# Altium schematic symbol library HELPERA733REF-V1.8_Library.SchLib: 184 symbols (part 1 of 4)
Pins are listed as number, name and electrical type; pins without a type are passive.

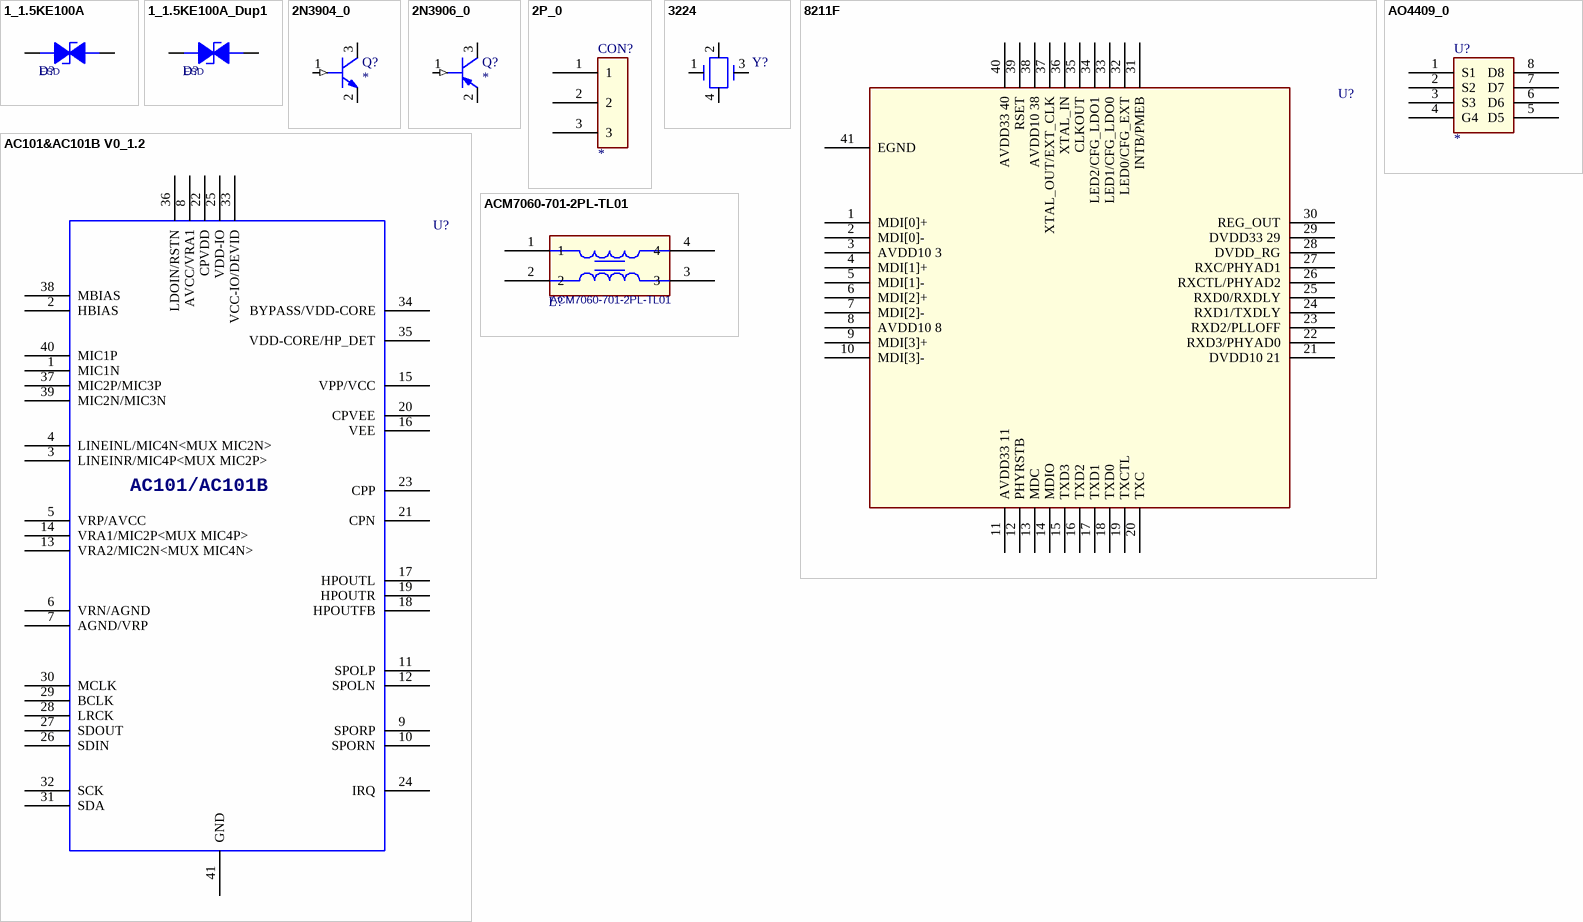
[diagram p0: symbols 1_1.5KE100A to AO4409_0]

## 1_1.5KE100A
designator D?, comment ESD
pins: 1 ANODE, 2 CATHODE

## 1_1.5KE100A_Dup1
designator D?, comment ESD
pins: 1 ANODE, 2 CATHODE

## 2N3904_0
designator Q?
pins: 1 BASE (in), 2 EMITTER, 3 COLLECTOR

## 2N3906_0
designator Q?
pins: 1 BASE (in), 2 EMITTER, 3 COLLECTOR

## 2P_0
designator CON?
pins: 1, 2, 3

## 3224
designator Y?, comment 25M-10pF-30ppm  (value not drawn)
Parameter: 插件无源晶振，HC-49S; ID: CR-S-P0019
pins: 1, 2, 3, 4

## 8211F
designator U?, comment RTL8211F-CG/RTL8211FD-CG  (value not drawn)
ID: OT-IC0192; Parameter: QFN40
pins: 1 MDI[0]+, 2 MDI[0]-, 3 AVDD10 3, 4 MDI[1]+, 5 MDI[1]-, 6 MDI[2]+, 7 MDI[2]-, 8 AVDD10 8, 9 MDI[3]+, 10 MDI[3]-, 11 AVDD33 11, 12 PHYRSTB, 13 MDC, 14 MDIO, 15 TXD3, 16 TXD2, 17 TXD1, 18 TXD0, 19 TXCTL, 20 TXC, 21 DVDD10 21, 22 RXD3/PHYAD0, 23 RXD2/PLLOFF, 24 RXD1/TXDLY, 25 RXD0/RXDLY, 26 RXCTL/PHYAD2, 27 RXC/PHYAD1, 28 DVDD_RG, 29 DVDD33 29, 30 REG_OUT, 31 INTB/PMEB, 32 LED0/CFG_EXT, 33 LED1/CFG_LDO0, 34 LED2/CFG_LDO1, 35 CLKOUT, 36 XTAL_IN, 37 XTAL_OUT/EXT_CLK, 38 AVDD10 38, 39 RSET, 40 AVDD33 40, 41 EGND

## AC101&AC101B V0_1.2
designator U?, comment AXP22x  (value not drawn)
pins: 1 MIC1N, 2 HBIAS, 3 LINEINR/MIC4P<MUX MIC2P>, 4 LINEINL/MIC4N<MUX MIC2N>, 5 VRP/AVCC, 6 VRN/AGND, 7 AGND/VRP, 8 AVCC/VRA1, 9 SPORP, 10 SPORN, 11 SPOLP, 12 SPOLN, 13 VRA2/MIC2N<MUX MIC4N>, 14 VRA1/MIC2P<MUX MIC4P>, 15 VPP/VCC, 16 VEE, 17 HPOUTL, 18 HPOUTFB, 19 HPOUTR, 20 CPVEE, 21 CPN, 22 CPVDD, 23 CPP, 24 IRQ, 25 VDD-IO, 26 SDIN, 27 SDOUT, 28 LRCK, 29 BCLK, 30 MCLK, 31 SDA, 32 SCK, 33 VCC-IO/DEVID, 34 BYPASS/VDD-CORE, 35 VDD-CORE/HP_DET, 36 LDOIN/RSTN, 37 MIC2P/MIC3P, 38 MBIAS, 39 MIC2N/MIC3N, 40 MIC1P, 41 GND

## ACM7060-701-2PL-TL01
designator L?
footprint SMD_7x6mm
pins: 1, 2, 3, 4

## AO4409_0
designator U?
pins: 1 S1, 2 S2, 3 S3, 4 G4, 5 D5, 6 D6, 7 D7, 8 D8

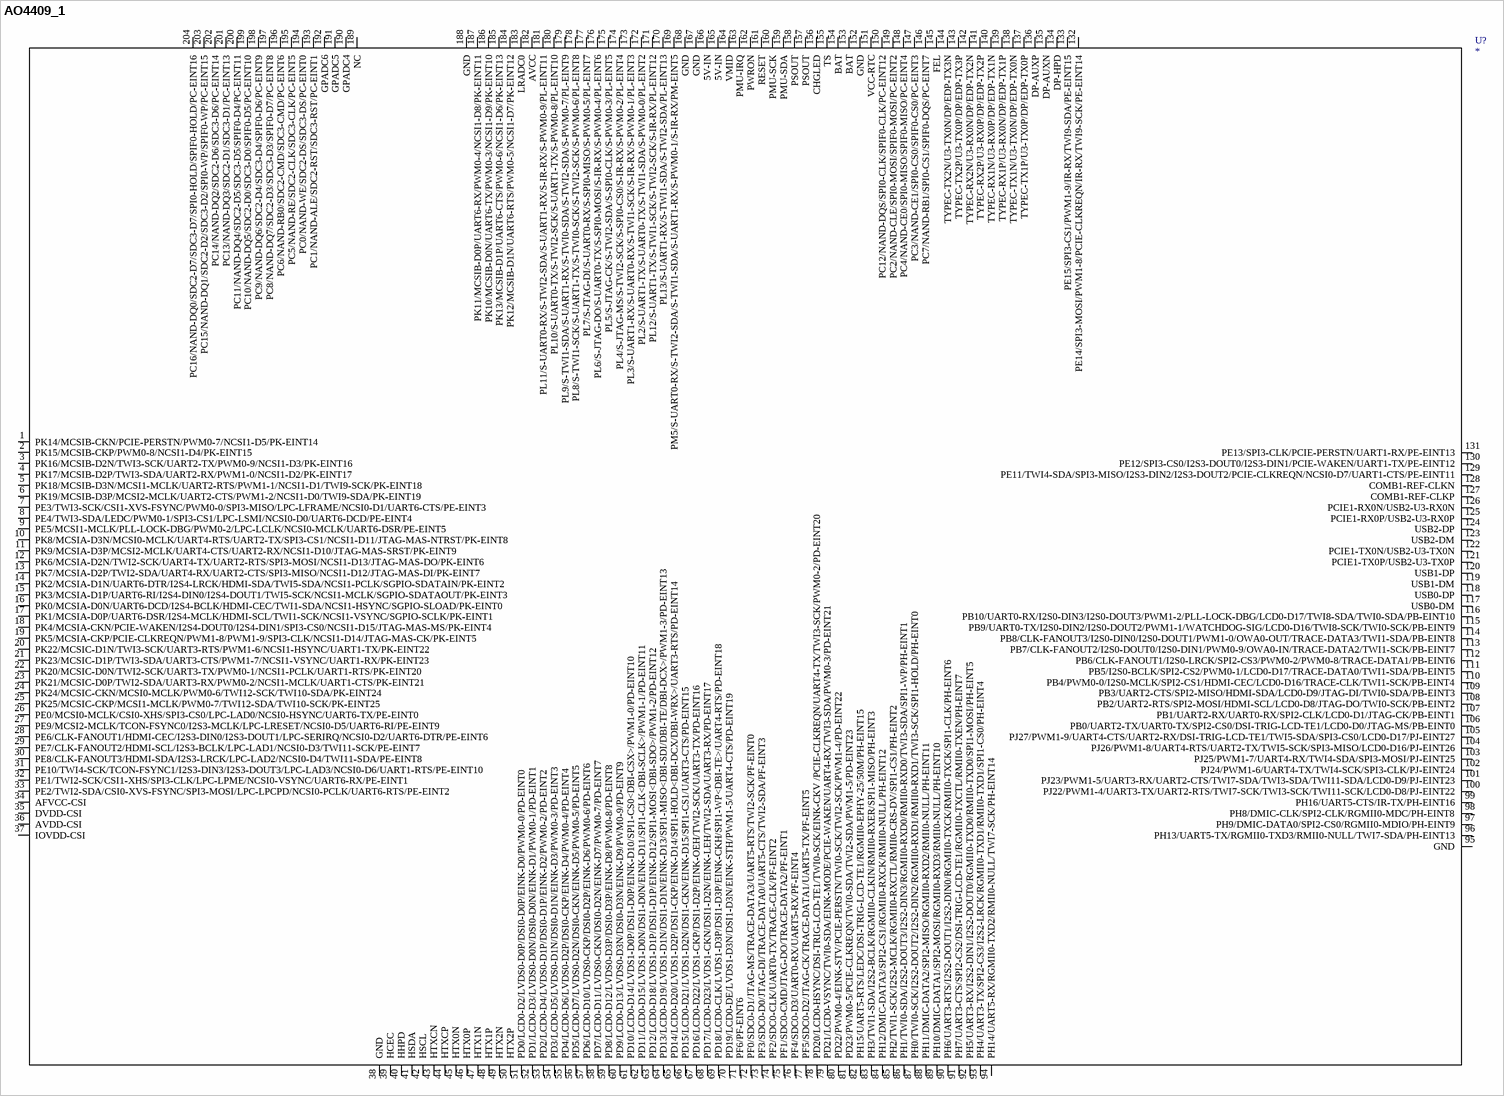
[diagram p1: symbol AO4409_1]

## AO4409_1
designator U?
pins: 1 PK14/MCSIB-CKN/PCIE-PERSTN/PWM0-7/NCSI1-D5/PK-EINT14, 2 PK15/MCSIB-CKP/PWM0-8/NCSI1-D4/PK-EINT15, 3 PK16/MCSIB-D2N/TWI3-SCK/UART2-TX/PWM0-9/NCSI1-D3/PK-EINT16, 4 PK17/MCSIB-D2P/TWI3-SDA/UART2-RX/PWM1-0/NCSI1-D2/PK-EINT17, 5 PK18/MCSIB-D3N/MCSI1-MCLK/UART2-RTS/PWM1-1/NCSI1-D1/TWI9-SCK/PK-EINT18, 6 PK19/MCSIB-D3P/MCSI2-MCLK/UART2-CTS/PWM1-2/NCSI1-D0/TWI9-SDA/PK-EINT19, 7 PE3/TWI3-SCK/CSI1-XVS-FSYNC/PWM0-0/SPI3-MISO/LPC-LFRAME/NCSI0-D1/UART6-CTS/PE-EINT3, 8 PE4/TWI3-SDA/LEDC/PWM0-1/SPI3-CS1/LPC-LSMI/NCSI0-D0/UART6-DCD/PE-EINT4, 9 PE5/MCSI1-MCLK/PLL-LOCK-DBG/PWM0-2/LPC-LCLK/NCSI0-MCLK/UART6-DSR/PE-EINT5, 10 PK8/MCSIA-D3N/MCSI0-MCLK/UART4-RTS/UART2-TX/SPI3-CS1/NCSI1-D11/JTAG-MAS-NTRST/PK-EINT8, 11 PK9/MCSIA-D3P/MCSI2-MCLK/UART4-CTS/UART2-RX/NCSI1-D10/JTAG-MAS-SRST/PK-EINT9, 12 PK6/MCSIA-D2N/TWI2-SCK/UART4-TX/UART2-RTS/SPI3-MOSI/NCSI1-D13/JTAG-MAS-DO/PK-EINT6, 13 PK7/MCSIA-D2P/TWI2-SDA/UART4-RX/UART2-CTS/SPI3-MISO/NCSI1-D12/JTAG-MAS-DI/PK-EINT7, 14 PK2/MCSIA-D1N/UART6-DTR/I2S4-LRCK/HDMI-SDA/TWI5-SDA/NCSI1-PCLK/SGPIO-SDATAIN/PK-EINT2, 15 PK3/MCSIA-D1P/UART6-RI/I2S4-DIN0/I2S4-DOUT1/TWI5-SCK/NCSI1-MCLK/SGPIO-SDATAOUT/PK-EINT3, 16 PK0/MCSIA-D0N/UART6-DCD/I2S4-BCLK/HDMI-CEC/TWI1-SDA/NCSI1-HSYNC/SGPIO-SLOAD/PK-EINT0, 17 PK1/MCSIA-D0P/UART6-DSR/I2S4-MCLK/HDMI-SCL/TWI1-SCK/NCSI1-VSYNC/SGPIO-SCLK/PK-EINT1, 18 PK4/MCSIA-CKN/PCIE-WAKEN/I2S4-DOUT0/I2S4-DIN1/SPI3-CS0/NCSI1-D15/JTAG-MAS-MS/PK-EINT4, 19 PK5/MCSIA-CKP/PCIE-CLKREQN/PWM1-8/PWM1-9/SPI3-CLK/NCSI1-D14/JTAG-MAS-CK/PK-EINT5, 20 PK22/MCSIC-D1N/TWI3-SCK/UART3-RTS/PWM1-6/NCSI1-HSYNC/UART1-TX/PK-EINT22, 21 PK23/MCSIC-D1P/TWI3-SDA/UART3-CTS/PWM1-7/NCSI1-VSYNC/UART1-RX/PK-EINT23, 22 PK20/MCSIC-D0N/TWI2-SCK/UART3-TX/PWM0-1/NCSI1-PCLK/UART1-RTS/PK-EINT20, 23 PK21/MCSIC-D0P/TWI2-SDA/UART3-RX/PWM0-2/NCSI1-MCLK/UART1-CTS/PK-EINT21, 24 PK24/MCSIC-CKN/MCSI0-MCLK/PWM0-6/TWI12-SCK/TWI10-SDA/PK-EINT24, 25 PK25/MCSIC-CKP/MCSI1-MCLK/PWM0-7/TWI12-SDA/TWI10-SCK/PK-EINT25, 26 PE0/MCSI0-MCLK/CSI0-XHS/SPI3-CS0/LPC-LAD0/NCSI0-HSYNC/UART6-TX/PE-EINT0, 27 PE9/MCSI2-MCLK/TCON-FSYNC0/I2S3-MCLK/LPC-LRESET/NCSI0-D5/UART6-RI/PE-EINT9, 28 PE6/CLK-FANOUT1/HDMI-CEC/I2S3-DIN0/I2S3-DOUT1/LPC-SERIRQ/NCSI0-D2/UART6-DTR/PE-EINT6, 29 PE7/CLK-FANOUT2/HDMI-SCL/I2S3-BCLK/LPC-LAD1/NCSI0-D3/TWI11-SCK/PE-EINT7, 30 PE8/CLK-FANOUT3/HDMI-SDA/I2S3-LRCK/LPC-LAD2/NCSI0-D4/TWI11-SDA/PE-EINT8, 31 PE10/TWI4-SCK/TCON-FSYNC1/I2S3-DIN3/I2S3-DOUT3/LPC-LAD3/NCSI0-D6/UART1-RTS/PE-EINT10, 32 PE1/TWI2-SCK/CSI1-XHS/SPI3-CLK/LPC-LPME/NCSI0-VSYNC/UART6-RX/PE-EINT1, 33 PE2/TWI2-SDA/CSI0-XVS-FSYNC/SPI3-MOSI/LPC-LPCPD/NCSI0-PCLK/UART6-RTS/PE-EINT2, 34 AFVCC-CSI, 35 DVDD-CSI, 36 AVDD-CSI, 37 IOVDD-CSI, 38 GND, 39 HCEC, 40 HHPD, 41 HSDA, 42 HSCL, 43 HTXCN, 44 HTXCP, 45 HTX0N, 46 HTX0P, 47 HTX1N, 48 HTX1P, 49 HTX2N, 50 HTX2P, 51 PD0/LCD0-D2/LVDS0-D0P/DSI0-D0P/EINK-D0/PWM0-0/PD-EINT0, 52 PD1/LCD0-D3/LVDS0-D0N/DSI0-D0N/EINK-D1/PWM0-1/PD-EINT1, 53 PD2/LCD0-D4/LVDS0-D1P/DSI0-D1P/EINK-D2/PWM0-2/PD-EINT2, 54 PD3/LCD0-D5/LVDS0-D1N/DSI0-D1N/EINK-D3/PWM0-3/PD-EINT3, 55 PD4/LCD0-D6/LVDS0-D2P/DSI0-CKP/EINK-D4/PWM0-4/PD-EINT4, 56 PD5/LCD0-D7/LVDS0-D2N/DSI0-CKN/EINK-D5/PWM0-5/PD-EINT5, 57 PD6/LCD0-D10/LVDS0-CKP/DSI0-D2P/EINK-D6/PWM0-6/PD-EINT6, 58 PD7/LCD0-D11/LVDS0-CKN/DSI0-D2N/EINK-D7/PWM0-7/PD-EINT7, 59 PD8/LCD0-D12/LVDS0-D3P/DSI0-D3P/EINK-D8/PWM0-8/PD-EINT8, 60 PD9/LCD0-D13/LVDS0-D3N/DSI0-D3N/EINK-D9/PWM0-9/PD-EINT9, 61 PD10/LCD0-D14/LVDS1-D0P/DSI1-D0P/EINK-D10/SPI1-CS0<DBI-CSX>/PWM1-0/PD-EINT10, 62 PD11/LCD0-D15/LVDS1-D0N/DSI1-D0N/EINK-D11/SPI1-CLK<DBI-SCLK>/PWM1-1/PD-EINT11, 63 PD12/LCD0-D18/LVDS1-D1P/DSI1-D1P/EINK-D12/SPI1-MOSI<DBI-SDO>/PWM1-2/PD-EINT12, 64 PD13/LCD0-D19/LVDS1-D1N/DSI1-D1N/EINK-D13/SPI1-MISO<DBI-SDI/DBI-TE/DBI-DCX>/PWM1-3/PD-EINT13, 65 PD14/LCD0-D20/LVDS1-D2P/DSI1-CKP/EINK-D14/SPI1-HOLD<DBI-DCX/DBI-WRX>/UART3-RTS/PD-EINT14, 66 PD15/LCD0-D21/LVDS1-D2N/DSI1-CKN/EINK-D15/SPI1-CS1/UART3-CTS/PD-EINT15, 67 PD16/LCD0-D22/LVDS1-CKP/DSI1-D2P/EINK-OEH/TWI2-SCK/UART3-TX/PD-EINT16, 68 PD17/LCD0-D23/LVDS1-CKN/DSI1-D2N/EINK-LEH/TWI2-SDA/UART3-RX/PD-EINT17, 69 PD18/LCD0-CLK/LVDS1-D3P/DSI1-D3P/EINK-CKH/SPI1-WP<DBI-TE>/UART4-RTS/PD-EINT18, 70 PD19/LCD0-DE/LVDS1-D3N/DSI1-D3N/EINK-STH/PWM1-5/UART4-CTS/PD-EINT19, 71 PF6/PF-EINT6, 72 PF0/SDC0-D1/JTAG-MS/TRACE-DATA3/UART5-RTS/TWI2-SCK/PF-EINT0, 73 PF3/SDC0-D0/JTAG-DI/TRACE-DATA0/UART5-CTS/TWI2-SDA/PF-EINT3, 74 PF2/SDC0-CLK/UART0-TX/TRACE-CLK/PF-EINT2, 75 PF1/SDC0-CMD/JTAG-DO/TRACE-DATA2/PF-EINT1, 76 PF4/SDC0-D3/UART0-RX/UART5-RX/PF-EINT4, 77 PF5/SDC0-D2/JTAG-CK/TRACE-DATA1/UART5-TX/PF-EINT5, 78 PD20/LCD0-HSYNC/DSI-TRIG-LCD-TE1/TWI0-SCK/EINK-CKV /PCIE-CLKREQN/UART4-TX/TWI3-SCK/PWM0-2/PD-EINT20, 79 PD21/LCD0-VSYNC/TWI0-SDA/EINK-MODE/PCIE-WAKEN/UART4-RX/TWI3-SDA/PWM0-3/PD-EINT21, 80 PD22/PWM0-4/EINK-STV/PCIE-PERSTN/TWI0-SCK/TWI2-SCK/PWM1-4/PD-EINT22, 81 PD23/PWM0-5/PCIE-CLKREQN/TWI0-SDA/TWI2-SDA/PWM1-5/PD-EINT23, 82 PH15/UART5-RTS/LEDC/DSI-TRIG-LCD-TE1/RGMII0-EPHY-25/50M/PH-EINT15, 83 PH3/TWI1-SDA/I2S2-BCLK/RGMII0-CLKIN/RMII0-RXER/SPI1-MISO/PH-EINT3, 84 PH12/DMIC-DATA3/SPI2-CS1/RGMII0-RXCK/RMII0-NULL/PH-EINT12, 85 PH2/TWI1-SCK/I2S2-MCLK/RGMII0-RXCTL/RMII0-CRS-DV/SPI1-CS1/PH-EINT2, 86 PH1/TWI0-SDA/I2S2-DOUT3/I2S2-DIN3/RGMII0-RXD0/RMII0-RXD0/TWI3-SDA/SPI1-WP/PH-EINT1, 87 PH0/TWI0-SCK/I2S2-DOUT2/I2S2-DIN2/RGMII0-RXD1/RMII0-RXD1/TWI3-SCK/SPI1-HOLD/PH-EINT0, 88 PH11/DMIC-DATA2/SPI2-MISO/RGMII0-RXD2/RMII0-NULL/PH-EINT11, 89 PH10/DMIC-DATA1/SPI2-MOSI/RGMII0-RXD3/RMII0-NULL/PH-EINT10, 90 PH6/UART3-RTS/I2S2-DOUT1/I2S2-DIN0/RGMII0-TXCK/RMII0-TXCK/SPI1-CLK/PH-EINT6, 91 PH7/UART3-CTS/SPI2-CS2/DSI-TRIG-LCD-TE1/RGMII0-TXCTL/RMII0-TXEN/PH-EINT7, 92 PH5/UART3-RX/I2S2-DIN1/I2S2-DOUT0/RGMII0-TXD0/RMII0-TXD0/SPI1-MOSI/PH-EINT5, 93 PH4/UART3-TX/SPI2-CS3/I2S2-LRCK/RGMII0-TXD1/RMII0-TXD1/SPI1-CS0/PH-EINT4, 94 PH14/UART5-RX/RGMII0-TXD2/RMII0-NULL/TWI7-SCK/PH-EINT14, 95 GND, 96 PH13/UART5-TX/RGMII0-TXD3/RMII0-NULL/TWI7-SDA/PH-EINT13, 97 PH9/DMIC-DATA0/SPI2-CS0/RGMII0-MDIO/PH-EINT9, 98 PH8/DMIC-CLK/SPI2-CLK/RGMII0-MDC/PH-EINT8, 99 PH16/UART5-CTS/IR-TX/PH-EINT16, 100 PJ22/PWM1-4/UART3-TX/UART2-RTS/TWI7-SCK/TWI3-SCK/TWI11-SCK/LCD0-D8/PJ-EINT22, 101 PJ23/PWM1-5/UART3-RX/UART2-CTS/TWI7-SDA/TWI3-SDA/TWI11-SDA/LCD0-D9/PJ-EINT23, 102 PJ24/PWM1-6/UART4-TX/TWI4-SCK/SPI3-CLK/PJ-EINT24, 103 PJ25/PWM1-7/UART4-RX/TWI4-SDA/SPI3-MOSI/PJ-EINT25, 104 PJ26/PWM1-8/UART4-RTS/UART2-TX/TWI5-SCK/SPI3-MISO/LCD0-D16/PJ-EINT26, 105 PJ27/PWM1-9/UART4-CTS/UART2-RX/DSI-TRIG-LCD-TE1/TWI5-SDA/SPI3-CS0/LCD0-D17/PJ-EINT27, 106 PB0/UART2-TX/UART0-TX/SPI2-CS0/DSI-TRIG-LCD-TE1/LCD0-D0/JTAG-MS/PB-EINT0, 107 PB1/UART2-RX/UART0-RX/SPI2-CLK/LCD0-D1/JTAG-CK/PB-EINT1, 108 PB2/UART2-RTS/SPI2-MOSI/HDMI-SCL/LCD0-D8/JTAG-DO/TWI0-SCK/PB-EINT2, 109 PB3/UART2-CTS/SPI2-MISO/HDMI-SDA/LCD0-D9/JTAG-DI/TWI0-SDA/PB-EINT3, 110 PB4/PWM0-0/I2S0-MCLK/SPI2-CS1/HDMI-CEC/LCD0-D16/TRACE-CLK/TWI1-SCK/PB-EINT4, 111 PB5/I2S0-BCLK/SPI2-CS2/PWM0-1/LCD0-D17/TRACE-DATA0/TWI1-SDA/PB-EINT5, 112 PB6/CLK-FANOUT1/I2S0-LRCK/SPI2-CS3/PWM0-2/PWM0-8/TRACE-DATA1/PB-EINT6, 113 PB7/CLK-FANOUT2/I2S0-DOUT0/I2S0-DIN1/PWM0-9/OWA0-IN/TRACE-DATA2/TWI1-SCK/PB-EINT7, 114 PB8/CLK-FANOUT3/I2S0-DIN0/I2S0-DOUT1/PWM1-0/OWA0-OUT/TRACE-DATA3/TWI1-SDA/PB-EINT8, 115 PB9/UART0-TX/I2S0-DIN2/I2S0-DOUT2/PWM1-1/WATCHDOG-SIG/LCD0-D16/TWI8-SCK/TWI0-SCK/PB-EINT9, 116 PB10/UART0-RX/I2S0-DIN3/I2S0-DOUT3/PWM1-2/PLL-LOCK-DBG/LCD0-D17/TWI8-SDA/TWI0-SDA/PB-EINT10, 117 USB0-DM, 118 USB0-DP, 119 USB1-DM, 120 USB1-DP, 121 PCIE1-TX0P/USB2-U3-TX0P, 122 PCIE1-TX0N/USB2-U3-TX0N, 123 USB2-DM, 124 USB2-DP, 125 PCIE1-RX0P/USB2-U3-RX0P, 126 PCIE1-RX0N/USB2-U3-RX0N, 127 COMB1-REF-CLKP, 128 COMB1-REF-CLKN, 129 PE11/TWI4-SDA/SPI3-MISO/I2S3-DIN2/I2S3-DOUT2/PCIE-CLKREQN/NCSI0-D7/UART1-CTS/PE-EINT11, 130 PE12/SPI3-CS0/I2S3-DOUT0/I2S3-DIN1/PCIE-WAKEN/UART1-TX/PE-EINT12, 131 PE13/SPI3-CLK/PCIE-PERSTN/UART1-RX/PE-EINT13, 132 PE14/SPI3-MOSI/PWM1-8/PCIE-CLKREQN/IR-RX/TWI9-SCK/PE-EINT14, 133 PE15/SPI3-CS1/PWM1-9/IR-RX/TWI9-SDA/PE-EINT15, 134 DP-HPD, 135 DP-AUXN, 136 DP-AUXP, 137 TYPEC-TX1P/U3-TX0P/DP/EDP-TX0P, 138 TYPEC-TX1N/U3-TX0N/DP/EDP-TX0N, 139 TYPEC-RX1P/U3-RX0N/DP/EDP-TX1P, 140 TYPEC-RX1N/U3-RX0P/DP/EDP-TX1N, 141 TYPEC-RX2P/U3-RX0P/DP/EDP-TX2P, 142 TYPEC-RX2N/U3-RX0N/DP/EDP-TX2N, 143 TYPEC-TX2P/U3-TX0P/DP/EDP-TX3P, 144 TYPEC-TX2N/U3-TX0N/DP/EDP-TX3N, 145 FEL, 146 PC7/NAND-RB1/SPI0-CS1/SPIF0-DQS/PC-EINT7, 147 PC3/NAND-CE1/SPI0-CS0/SPIF0-CS0/PC-EINT3, 148 PC4/NAND-CE0/SPI0-MISO/SPIF0-MISO/PC-EINT4, 149 PC2/NAND-CLE/SPI0-MOSI/SPIF0-MOSI/PC-EINT2, 150 PC12/NAND-DQS/SPI0-CLK/SPIF0-CLK/PC-EINT12, 151 VCC-RTC, 152 GND, 153 BAT, 154 BAT, 155 TS, 156 CHGLED, 157 PSOUT, 158 PSOUT, 159 PMU-SDA, 160 PMU-SCK, 161 RESET, 162 PWRON, 163 PMU-IRQ, 164 VMID, 165 5V-IN, 166 5V-IN, 167 GND, 168 GND, 169 PM5/S-UART0-RX/S-TWI2-SDA/S-TWI1-SDA/S-UART1-RX/S-PWM0-1/S-IR-RX/PM-EINT5, 170 PL13/S-UART1-RX/S-TWI1-SDA/S-TWI2-SDA/PL-EINT13, 171 PL12/S-UART1-TX/S-TWI1-SCK/S-TWI2-SCK/S-IR-RX/PL-EINT12, 172 PL2/S-UART1-TX/S-UART0-TX/S-TWI1-SDA/S-PWM0-0/PL-EINT2, 173 PL3/S-UART1-RX/S-UART0-RX/S-TWI1-SCK/S-IR-RX/S-PWM0-1/PL-EINT3, 174 PL4/S-JTAG-MS/S-TWI2-SCK/S-SPI0-CS0/S-IR-RX/S-PWM0-2/PL-EINT4, 175 PL5/S-JTAG-CK/S-TWI2-SDA/S-SPI0-CLK/S-PWM0-3/PL-EINT5, 176 PL6/S-JTAG-DO/S-UART0-TX/S-SPI0-MOSI/S-IR-RX/S-PWM0-4/PL-EINT6, 177 PL7/S-JTAG-DI/S-UART0-RX/S-SPI0-MISO/S-PWM0-5/PL-EINT7, 178 PL8/S-TWI1-SCK/S-UART1-TX/S-TWI0-SCK/S-TWI2-SCK/S-PWM0-6/PL-EINT8, 179 PL9/S-TWI1-SDA/S-UART1-RX/S-TWI0-SDA/S-TWI2-SDA/S-PWM0-7/PL-EINT9, 180 PL10/S-UART0-TX/S-TWI2-SCK/S-UART1-TX/S-PWM0-8/PL-EINT10, 181 PL11/S-UART0-RX/S-TWI2-SDA/S-UART1-RX/S-IR-RX/S-PWM0-9/PL-EINT11, 182 AVCC, 183 LRADC0, 184 PK12/MCSIB-D1N/UART6-RTS/PWM0-5/NCSI1-D7/PK-EINT12, 185 PK13/MCSIB-D1P/UART6-CTS/PWM0-6/NCSI1-D6/PK-EINT13, 186 PK10/MCSIB-D0N/UART6-TX/PWM0-3/NCSI1-D9/PK-EINT10, 187 PK11/MCSIB-D0P/UART6-RX/PWM0-4/NCSI1-D8/PK-EINT11, 188 GND, 189 NC, 190 GPADC4, 191 GPADC5, 192 GPADC6, 193 PC1/NAND-ALE/SDC2-RST/SDC3-RST/PC-EINT1, 194 PC0/NAND-WE/SDC2-DS/SDC3-DS/PC-EINT0, 195 PC5/NAND-RE/SDC2-CLK/SDC3-CLK/PC-EINT5, 196 PC6/NAND-RB0/SDC2-CMD/SDC3-CMD/PC-EINT6, 197 PC8/NAND-DQ7/SDC2-D3/SDC3-D3/SPIF0-D7/PC-EINT8, 198 PC9/NAND-DQ6/SDC2-D4/SDC3-D4/SPIF0-D6/PC-EINT9, 199 PC10/NAND-DQ5/SDC2-D0/SDC3-D0/SPIF0-D5/PC-EINT10, 200 PC11/NAND-DQ4/SDC2-D5/SDC3-D5/SPIF0-D4/PC-EINT11, 201 PC13/NAND-DQ3/SDC2-D1/SDC3-D1/PC-EINT13, 202 PC14/NAND-DQ2/SDC2-D6/SDC3-D6/PC-EINT14, 203 PC15/NAND-DQ1/SDC2-D2/SDC3-D2/SPI0-WP/SPIF0-WP/PC-EINT15, 204 PC16/NAND-DQ0/SDC2-D7/SDC3-D7/SPI0-HOLD/SPIF0-HOLD/PC-EINT16

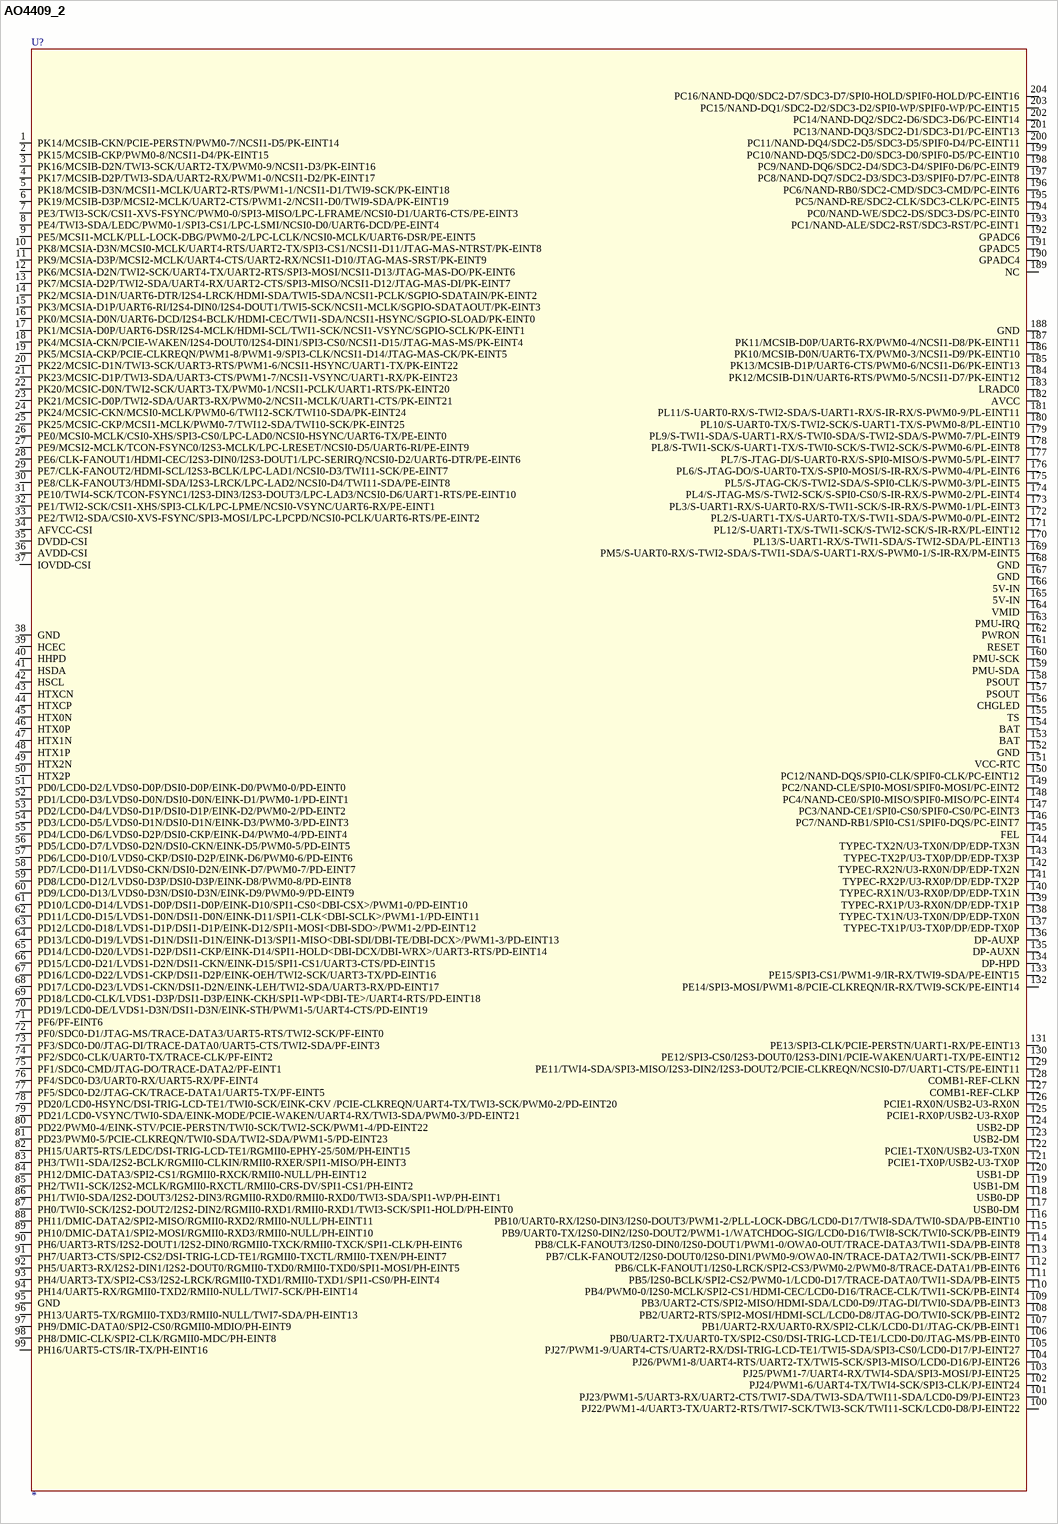
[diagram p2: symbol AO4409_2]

## AO4409_2
designator U?
pins: 1 PK14/MCSIB-CKN/PCIE-PERSTN/PWM0-7/NCSI1-D5/PK-EINT14, 2 PK15/MCSIB-CKP/PWM0-8/NCSI1-D4/PK-EINT15, 3 PK16/MCSIB-D2N/TWI3-SCK/UART2-TX/PWM0-9/NCSI1-D3/PK-EINT16, 4 PK17/MCSIB-D2P/TWI3-SDA/UART2-RX/PWM1-0/NCSI1-D2/PK-EINT17, 5 PK18/MCSIB-D3N/MCSI1-MCLK/UART2-RTS/PWM1-1/NCSI1-D1/TWI9-SCK/PK-EINT18, 6 PK19/MCSIB-D3P/MCSI2-MCLK/UART2-CTS/PWM1-2/NCSI1-D0/TWI9-SDA/PK-EINT19, 7 PE3/TWI3-SCK/CSI1-XVS-FSYNC/PWM0-0/SPI3-MISO/LPC-LFRAME/NCSI0-D1/UART6-CTS/PE-EINT3, 8 PE4/TWI3-SDA/LEDC/PWM0-1/SPI3-CS1/LPC-LSMI/NCSI0-D0/UART6-DCD/PE-EINT4, 9 PE5/MCSI1-MCLK/PLL-LOCK-DBG/PWM0-2/LPC-LCLK/NCSI0-MCLK/UART6-DSR/PE-EINT5, 10 PK8/MCSIA-D3N/MCSI0-MCLK/UART4-RTS/UART2-TX/SPI3-CS1/NCSI1-D11/JTAG-MAS-NTRST/PK-EINT8, 11 PK9/MCSIA-D3P/MCSI2-MCLK/UART4-CTS/UART2-RX/NCSI1-D10/JTAG-MAS-SRST/PK-EINT9, 12 PK6/MCSIA-D2N/TWI2-SCK/UART4-TX/UART2-RTS/SPI3-MOSI/NCSI1-D13/JTAG-MAS-DO/PK-EINT6, 13 PK7/MCSIA-D2P/TWI2-SDA/UART4-RX/UART2-CTS/SPI3-MISO/NCSI1-D12/JTAG-MAS-DI/PK-EINT7, 14 PK2/MCSIA-D1N/UART6-DTR/I2S4-LRCK/HDMI-SDA/TWI5-SDA/NCSI1-PCLK/SGPIO-SDATAIN/PK-EINT2, 15 PK3/MCSIA-D1P/UART6-RI/I2S4-DIN0/I2S4-DOUT1/TWI5-SCK/NCSI1-MCLK/SGPIO-SDATAOUT/PK-EINT3, 16 PK0/MCSIA-D0N/UART6-DCD/I2S4-BCLK/HDMI-CEC/TWI1-SDA/NCSI1-HSYNC/SGPIO-SLOAD/PK-EINT0, 17 PK1/MCSIA-D0P/UART6-DSR/I2S4-MCLK/HDMI-SCL/TWI1-SCK/NCSI1-VSYNC/SGPIO-SCLK/PK-EINT1, 18 PK4/MCSIA-CKN/PCIE-WAKEN/I2S4-DOUT0/I2S4-DIN1/SPI3-CS0/NCSI1-D15/JTAG-MAS-MS/PK-EINT4, 19 PK5/MCSIA-CKP/PCIE-CLKREQN/PWM1-8/PWM1-9/SPI3-CLK/NCSI1-D14/JTAG-MAS-CK/PK-EINT5, 20 PK22/MCSIC-D1N/TWI3-SCK/UART3-RTS/PWM1-6/NCSI1-HSYNC/UART1-TX/PK-EINT22, 21 PK23/MCSIC-D1P/TWI3-SDA/UART3-CTS/PWM1-7/NCSI1-VSYNC/UART1-RX/PK-EINT23, 22 PK20/MCSIC-D0N/TWI2-SCK/UART3-TX/PWM0-1/NCSI1-PCLK/UART1-RTS/PK-EINT20, 23 PK21/MCSIC-D0P/TWI2-SDA/UART3-RX/PWM0-2/NCSI1-MCLK/UART1-CTS/PK-EINT21, 24 PK24/MCSIC-CKN/MCSI0-MCLK/PWM0-6/TWI12-SCK/TWI10-SDA/PK-EINT24, 25 PK25/MCSIC-CKP/MCSI1-MCLK/PWM0-7/TWI12-SDA/TWI10-SCK/PK-EINT25, 26 PE0/MCSI0-MCLK/CSI0-XHS/SPI3-CS0/LPC-LAD0/NCSI0-HSYNC/UART6-TX/PE-EINT0, 27 PE9/MCSI2-MCLK/TCON-FSYNC0/I2S3-MCLK/LPC-LRESET/NCSI0-D5/UART6-RI/PE-EINT9, 28 PE6/CLK-FANOUT1/HDMI-CEC/I2S3-DIN0/I2S3-DOUT1/LPC-SERIRQ/NCSI0-D2/UART6-DTR/PE-EINT6, 29 PE7/CLK-FANOUT2/HDMI-SCL/I2S3-BCLK/LPC-LAD1/NCSI0-D3/TWI11-SCK/PE-EINT7, 30 PE8/CLK-FANOUT3/HDMI-SDA/I2S3-LRCK/LPC-LAD2/NCSI0-D4/TWI11-SDA/PE-EINT8, 31 PE10/TWI4-SCK/TCON-FSYNC1/I2S3-DIN3/I2S3-DOUT3/LPC-LAD3/NCSI0-D6/UART1-RTS/PE-EINT10, 32 PE1/TWI2-SCK/CSI1-XHS/SPI3-CLK/LPC-LPME/NCSI0-VSYNC/UART6-RX/PE-EINT1, 33 PE2/TWI2-SDA/CSI0-XVS-FSYNC/SPI3-MOSI/LPC-LPCPD/NCSI0-PCLK/UART6-RTS/PE-EINT2, 34 AFVCC-CSI, 35 DVDD-CSI, 36 AVDD-CSI, 37 IOVDD-CSI, 38 GND, 39 HCEC, 40 HHPD, 41 HSDA, 42 HSCL, 43 HTXCN, 44 HTXCP, 45 HTX0N, 46 HTX0P, 47 HTX1N, 48 HTX1P, 49 HTX2N, 50 HTX2P, 51 PD0/LCD0-D2/LVDS0-D0P/DSI0-D0P/EINK-D0/PWM0-0/PD-EINT0, 52 PD1/LCD0-D3/LVDS0-D0N/DSI0-D0N/EINK-D1/PWM0-1/PD-EINT1, 53 PD2/LCD0-D4/LVDS0-D1P/DSI0-D1P/EINK-D2/PWM0-2/PD-EINT2, 54 PD3/LCD0-D5/LVDS0-D1N/DSI0-D1N/EINK-D3/PWM0-3/PD-EINT3, 55 PD4/LCD0-D6/LVDS0-D2P/DSI0-CKP/EINK-D4/PWM0-4/PD-EINT4, 56 PD5/LCD0-D7/LVDS0-D2N/DSI0-CKN/EINK-D5/PWM0-5/PD-EINT5, 57 PD6/LCD0-D10/LVDS0-CKP/DSI0-D2P/EINK-D6/PWM0-6/PD-EINT6, 58 PD7/LCD0-D11/LVDS0-CKN/DSI0-D2N/EINK-D7/PWM0-7/PD-EINT7, 59 PD8/LCD0-D12/LVDS0-D3P/DSI0-D3P/EINK-D8/PWM0-8/PD-EINT8, 60 PD9/LCD0-D13/LVDS0-D3N/DSI0-D3N/EINK-D9/PWM0-9/PD-EINT9, 61 PD10/LCD0-D14/LVDS1-D0P/DSI1-D0P/EINK-D10/SPI1-CS0<DBI-CSX>/PWM1-0/PD-EINT10, 62 PD11/LCD0-D15/LVDS1-D0N/DSI1-D0N/EINK-D11/SPI1-CLK<DBI-SCLK>/PWM1-1/PD-EINT11, 63 PD12/LCD0-D18/LVDS1-D1P/DSI1-D1P/EINK-D12/SPI1-MOSI<DBI-SDO>/PWM1-2/PD-EINT12, 64 PD13/LCD0-D19/LVDS1-D1N/DSI1-D1N/EINK-D13/SPI1-MISO<DBI-SDI/DBI-TE/DBI-DCX>/PWM1-3/PD-EINT13, 65 PD14/LCD0-D20/LVDS1-D2P/DSI1-CKP/EINK-D14/SPI1-HOLD<DBI-DCX/DBI-WRX>/UART3-RTS/PD-EINT14, 66 PD15/LCD0-D21/LVDS1-D2N/DSI1-CKN/EINK-D15/SPI1-CS1/UART3-CTS/PD-EINT15, 67 PD16/LCD0-D22/LVDS1-CKP/DSI1-D2P/EINK-OEH/TWI2-SCK/UART3-TX/PD-EINT16, 68 PD17/LCD0-D23/LVDS1-CKN/DSI1-D2N/EINK-LEH/TWI2-SDA/UART3-RX/PD-EINT17, 69 PD18/LCD0-CLK/LVDS1-D3P/DSI1-D3P/EINK-CKH/SPI1-WP<DBI-TE>/UART4-RTS/PD-EINT18, 70 PD19/LCD0-DE/LVDS1-D3N/DSI1-D3N/EINK-STH/PWM1-5/UART4-CTS/PD-EINT19, 71 PF6/PF-EINT6, 72 PF0/SDC0-D1/JTAG-MS/TRACE-DATA3/UART5-RTS/TWI2-SCK/PF-EINT0, 73 PF3/SDC0-D0/JTAG-DI/TRACE-DATA0/UART5-CTS/TWI2-SDA/PF-EINT3, 74 PF2/SDC0-CLK/UART0-TX/TRACE-CLK/PF-EINT2, 75 PF1/SDC0-CMD/JTAG-DO/TRACE-DATA2/PF-EINT1, 76 PF4/SDC0-D3/UART0-RX/UART5-RX/PF-EINT4, 77 PF5/SDC0-D2/JTAG-CK/TRACE-DATA1/UART5-TX/PF-EINT5, 78 PD20/LCD0-HSYNC/DSI-TRIG-LCD-TE1/TWI0-SCK/EINK-CKV /PCIE-CLKREQN/UART4-TX/TWI3-SCK/PWM0-2/PD-EINT20, 79 PD21/LCD0-VSYNC/TWI0-SDA/EINK-MODE/PCIE-WAKEN/UART4-RX/TWI3-SDA/PWM0-3/PD-EINT21, 80 PD22/PWM0-4/EINK-STV/PCIE-PERSTN/TWI0-SCK/TWI2-SCK/PWM1-4/PD-EINT22, 81 PD23/PWM0-5/PCIE-CLKREQN/TWI0-SDA/TWI2-SDA/PWM1-5/PD-EINT23, 82 PH15/UART5-RTS/LEDC/DSI-TRIG-LCD-TE1/RGMII0-EPHY-25/50M/PH-EINT15, 83 PH3/TWI1-SDA/I2S2-BCLK/RGMII0-CLKIN/RMII0-RXER/SPI1-MISO/PH-EINT3, 84 PH12/DMIC-DATA3/SPI2-CS1/RGMII0-RXCK/RMII0-NULL/PH-EINT12, 85 PH2/TWI1-SCK/I2S2-MCLK/RGMII0-RXCTL/RMII0-CRS-DV/SPI1-CS1/PH-EINT2, 86 PH1/TWI0-SDA/I2S2-DOUT3/I2S2-DIN3/RGMII0-RXD0/RMII0-RXD0/TWI3-SDA/SPI1-WP/PH-EINT1, 87 PH0/TWI0-SCK/I2S2-DOUT2/I2S2-DIN2/RGMII0-RXD1/RMII0-RXD1/TWI3-SCK/SPI1-HOLD/PH-EINT0, 88 PH11/DMIC-DATA2/SPI2-MISO/RGMII0-RXD2/RMII0-NULL/PH-EINT11, 89 PH10/DMIC-DATA1/SPI2-MOSI/RGMII0-RXD3/RMII0-NULL/PH-EINT10, 90 PH6/UART3-RTS/I2S2-DOUT1/I2S2-DIN0/RGMII0-TXCK/RMII0-TXCK/SPI1-CLK/PH-EINT6, 91 PH7/UART3-CTS/SPI2-CS2/DSI-TRIG-LCD-TE1/RGMII0-TXCTL/RMII0-TXEN/PH-EINT7, 92 PH5/UART3-RX/I2S2-DIN1/I2S2-DOUT0/RGMII0-TXD0/RMII0-TXD0/SPI1-MOSI/PH-EINT5, 93 PH4/UART3-TX/SPI2-CS3/I2S2-LRCK/RGMII0-TXD1/RMII0-TXD1/SPI1-CS0/PH-EINT4, 94 PH14/UART5-RX/RGMII0-TXD2/RMII0-NULL/TWI7-SCK/PH-EINT14, 95 GND, 96 PH13/UART5-TX/RGMII0-TXD3/RMII0-NULL/TWI7-SDA/PH-EINT13, 97 PH9/DMIC-DATA0/SPI2-CS0/RGMII0-MDIO/PH-EINT9, 98 PH8/DMIC-CLK/SPI2-CLK/RGMII0-MDC/PH-EINT8, 99 PH16/UART5-CTS/IR-TX/PH-EINT16, 100 PJ22/PWM1-4/UART3-TX/UART2-RTS/TWI7-SCK/TWI3-SCK/TWI11-SCK/LCD0-D8/PJ-EINT22, 101 PJ23/PWM1-5/UART3-RX/UART2-CTS/TWI7-SDA/TWI3-SDA/TWI11-SDA/LCD0-D9/PJ-EINT23, 102 PJ24/PWM1-6/UART4-TX/TWI4-SCK/SPI3-CLK/PJ-EINT24, 103 PJ25/PWM1-7/UART4-RX/TWI4-SDA/SPI3-MOSI/PJ-EINT25, 104 PJ26/PWM1-8/UART4-RTS/UART2-TX/TWI5-SCK/SPI3-MISO/LCD0-D16/PJ-EINT26, 105 PJ27/PWM1-9/UART4-CTS/UART2-RX/DSI-TRIG-LCD-TE1/TWI5-SDA/SPI3-CS0/LCD0-D17/PJ-EINT27, 106 PB0/UART2-TX/UART0-TX/SPI2-CS0/DSI-TRIG-LCD-TE1/LCD0-D0/JTAG-MS/PB-EINT0, 107 PB1/UART2-RX/UART0-RX/SPI2-CLK/LCD0-D1/JTAG-CK/PB-EINT1, 108 PB2/UART2-RTS/SPI2-MOSI/HDMI-SCL/LCD0-D8/JTAG-DO/TWI0-SCK/PB-EINT2, 109 PB3/UART2-CTS/SPI2-MISO/HDMI-SDA/LCD0-D9/JTAG-DI/TWI0-SDA/PB-EINT3, 110 PB4/PWM0-0/I2S0-MCLK/SPI2-CS1/HDMI-CEC/LCD0-D16/TRACE-CLK/TWI1-SCK/PB-EINT4, 111 PB5/I2S0-BCLK/SPI2-CS2/PWM0-1/LCD0-D17/TRACE-DATA0/TWI1-SDA/PB-EINT5, 112 PB6/CLK-FANOUT1/I2S0-LRCK/SPI2-CS3/PWM0-2/PWM0-8/TRACE-DATA1/PB-EINT6, 113 PB7/CLK-FANOUT2/I2S0-DOUT0/I2S0-DIN1/PWM0-9/OWA0-IN/TRACE-DATA2/TWI1-SCK/PB-EINT7, 114 PB8/CLK-FANOUT3/I2S0-DIN0/I2S0-DOUT1/PWM1-0/OWA0-OUT/TRACE-DATA3/TWI1-SDA/PB-EINT8, 115 PB9/UART0-TX/I2S0-DIN2/I2S0-DOUT2/PWM1-1/WATCHDOG-SIG/LCD0-D16/TWI8-SCK/TWI0-SCK/PB-EINT9, 116 PB10/UART0-RX/I2S0-DIN3/I2S0-DOUT3/PWM1-2/PLL-LOCK-DBG/LCD0-D17/TWI8-SDA/TWI0-SDA/PB-EINT10, 117 USB0-DM, 118 USB0-DP, 119 USB1-DM, 120 USB1-DP, 121 PCIE1-TX0P/USB2-U3-TX0P, 122 PCIE1-TX0N/USB2-U3-TX0N, 123 USB2-DM, 124 USB2-DP, 125 PCIE1-RX0P/USB2-U3-RX0P, 126 PCIE1-RX0N/USB2-U3-RX0N, 127 COMB1-REF-CLKP, 128 COMB1-REF-CLKN, 129 PE11/TWI4-SDA/SPI3-MISO/I2S3-DIN2/I2S3-DOUT2/PCIE-CLKREQN/NCSI0-D7/UART1-CTS/PE-EINT11, 130 PE12/SPI3-CS0/I2S3-DOUT0/I2S3-DIN1/PCIE-WAKEN/UART1-TX/PE-EINT12, 131 PE13/SPI3-CLK/PCIE-PERSTN/UART1-RX/PE-EINT13, 132 PE14/SPI3-MOSI/PWM1-8/PCIE-CLKREQN/IR-RX/TWI9-SCK/PE-EINT14, 133 PE15/SPI3-CS1/PWM1-9/IR-RX/TWI9-SDA/PE-EINT15, 134 DP-HPD, 135 DP-AUXN, 136 DP-AUXP, 137 TYPEC-TX1P/U3-TX0P/DP/EDP-TX0P, 138 TYPEC-TX1N/U3-TX0N/DP/EDP-TX0N, 139 TYPEC-RX1P/U3-RX0N/DP/EDP-TX1P, 140 TYPEC-RX1N/U3-RX0P/DP/EDP-TX1N, 141 TYPEC-RX2P/U3-RX0P/DP/EDP-TX2P, 142 TYPEC-RX2N/U3-RX0N/DP/EDP-TX2N, 143 TYPEC-TX2P/U3-TX0P/DP/EDP-TX3P, 144 TYPEC-TX2N/U3-TX0N/DP/EDP-TX3N, 145 FEL, 146 PC7/NAND-RB1/SPI0-CS1/SPIF0-DQS/PC-EINT7, 147 PC3/NAND-CE1/SPI0-CS0/SPIF0-CS0/PC-EINT3, 148 PC4/NAND-CE0/SPI0-MISO/SPIF0-MISO/PC-EINT4, 149 PC2/NAND-CLE/SPI0-MOSI/SPIF0-MOSI/PC-EINT2, 150 PC12/NAND-DQS/SPI0-CLK/SPIF0-CLK/PC-EINT12, 151 VCC-RTC, 152 GND, 153 BAT, 154 BAT, 155 TS, 156 CHGLED, 157 PSOUT, 158 PSOUT, 159 PMU-SDA, 160 PMU-SCK, 161 RESET, 162 PWRON, 163 PMU-IRQ, 164 VMID, 165 5V-IN, 166 5V-IN, 167 GND, 168 GND, 169 PM5/S-UART0-RX/S-TWI2-SDA/S-TWI1-SDA/S-UART1-RX/S-PWM0-1/S-IR-RX/PM-EINT5, 170 PL13/S-UART1-RX/S-TWI1-SDA/S-TWI2-SDA/PL-EINT13, 171 PL12/S-UART1-TX/S-TWI1-SCK/S-TWI2-SCK/S-IR-RX/PL-EINT12, 172 PL2/S-UART1-TX/S-UART0-TX/S-TWI1-SDA/S-PWM0-0/PL-EINT2, 173 PL3/S-UART1-RX/S-UART0-RX/S-TWI1-SCK/S-IR-RX/S-PWM0-1/PL-EINT3, 174 PL4/S-JTAG-MS/S-TWI2-SCK/S-SPI0-CS0/S-IR-RX/S-PWM0-2/PL-EINT4, 175 PL5/S-JTAG-CK/S-TWI2-SDA/S-SPI0-CLK/S-PWM0-3/PL-EINT5, 176 PL6/S-JTAG-DO/S-UART0-TX/S-SPI0-MOSI/S-IR-RX/S-PWM0-4/PL-EINT6, 177 PL7/S-JTAG-DI/S-UART0-RX/S-SPI0-MISO/S-PWM0-5/PL-EINT7, 178 PL8/S-TWI1-SCK/S-UART1-TX/S-TWI0-SCK/S-TWI2-SCK/S-PWM0-6/PL-EINT8, 179 PL9/S-TWI1-SDA/S-UART1-RX/S-TWI0-SDA/S-TWI2-SDA/S-PWM0-7/PL-EINT9, 180 PL10/S-UART0-TX/S-TWI2-SCK/S-UART1-TX/S-PWM0-8/PL-EINT10, 181 PL11/S-UART0-RX/S-TWI2-SDA/S-UART1-RX/S-IR-RX/S-PWM0-9/PL-EINT11, 182 AVCC, 183 LRADC0, 184 PK12/MCSIB-D1N/UART6-RTS/PWM0-5/NCSI1-D7/PK-EINT12, 185 PK13/MCSIB-D1P/UART6-CTS/PWM0-6/NCSI1-D6/PK-EINT13, 186 PK10/MCSIB-D0N/UART6-TX/PWM0-3/NCSI1-D9/PK-EINT10, 187 PK11/MCSIB-D0P/UART6-RX/PWM0-4/NCSI1-D8/PK-EINT11, 188 GND, 189 NC, 190 GPADC4, 191 GPADC5, 192 GPADC6, 193 PC1/NAND-ALE/SDC2-RST/SDC3-RST/PC-EINT1, 194 PC0/NAND-WE/SDC2-DS/SDC3-DS/PC-EINT0, 195 PC5/NAND-RE/SDC2-CLK/SDC3-CLK/PC-EINT5, 196 PC6/NAND-RB0/SDC2-CMD/SDC3-CMD/PC-EINT6, 197 PC8/NAND-DQ7/SDC2-D3/SDC3-D3/SPIF0-D7/PC-EINT8, 198 PC9/NAND-DQ6/SDC2-D4/SDC3-D4/SPIF0-D6/PC-EINT9, 199 PC10/NAND-DQ5/SDC2-D0/SDC3-D0/SPIF0-D5/PC-EINT10, 200 PC11/NAND-DQ4/SDC2-D5/SDC3-D5/SPIF0-D4/PC-EINT11, 201 PC13/NAND-DQ3/SDC2-D1/SDC3-D1/PC-EINT13, 202 PC14/NAND-DQ2/SDC2-D6/SDC3-D6/PC-EINT14, 203 PC15/NAND-DQ1/SDC2-D2/SDC3-D2/SPI0-WP/SPIF0-WP/PC-EINT15, 204 PC16/NAND-DQ0/SDC2-D7/SDC3-D7/SPI0-HOLD/SPIF0-HOLD/PC-EINT16

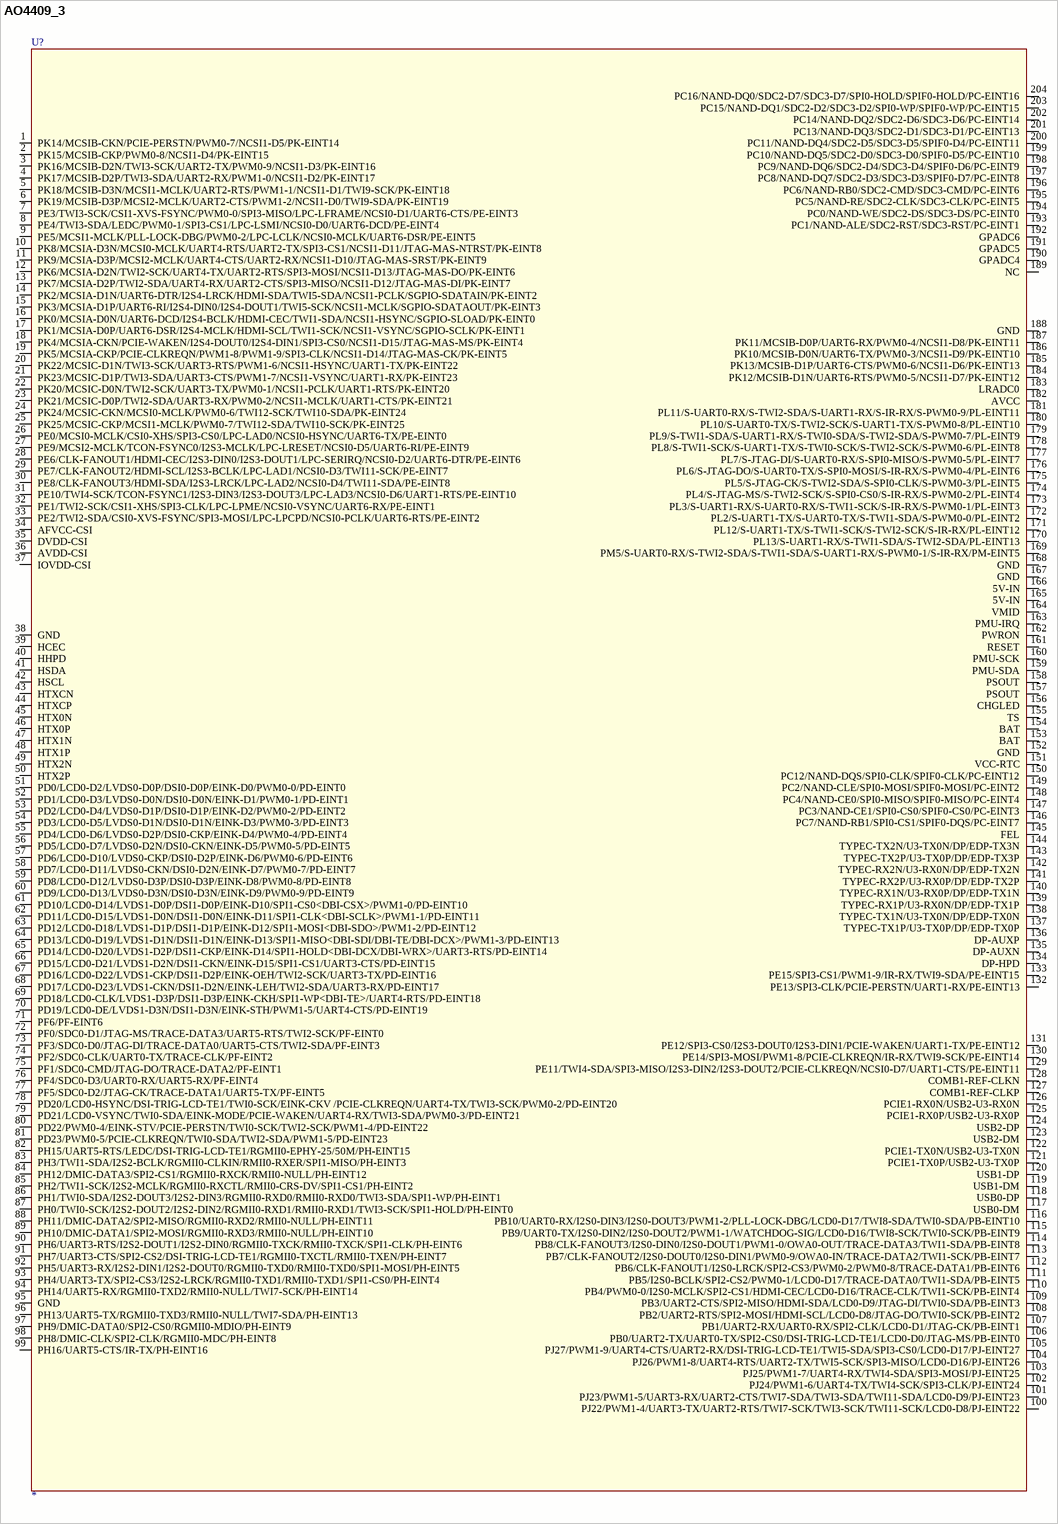
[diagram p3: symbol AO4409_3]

## AO4409_3
designator U?
pins: 1 PK14/MCSIB-CKN/PCIE-PERSTN/PWM0-7/NCSI1-D5/PK-EINT14, 2 PK15/MCSIB-CKP/PWM0-8/NCSI1-D4/PK-EINT15, 3 PK16/MCSIB-D2N/TWI3-SCK/UART2-TX/PWM0-9/NCSI1-D3/PK-EINT16, 4 PK17/MCSIB-D2P/TWI3-SDA/UART2-RX/PWM1-0/NCSI1-D2/PK-EINT17, 5 PK18/MCSIB-D3N/MCSI1-MCLK/UART2-RTS/PWM1-1/NCSI1-D1/TWI9-SCK/PK-EINT18, 6 PK19/MCSIB-D3P/MCSI2-MCLK/UART2-CTS/PWM1-2/NCSI1-D0/TWI9-SDA/PK-EINT19, 7 PE3/TWI3-SCK/CSI1-XVS-FSYNC/PWM0-0/SPI3-MISO/LPC-LFRAME/NCSI0-D1/UART6-CTS/PE-EINT3, 8 PE4/TWI3-SDA/LEDC/PWM0-1/SPI3-CS1/LPC-LSMI/NCSI0-D0/UART6-DCD/PE-EINT4, 9 PE5/MCSI1-MCLK/PLL-LOCK-DBG/PWM0-2/LPC-LCLK/NCSI0-MCLK/UART6-DSR/PE-EINT5, 10 PK8/MCSIA-D3N/MCSI0-MCLK/UART4-RTS/UART2-TX/SPI3-CS1/NCSI1-D11/JTAG-MAS-NTRST/PK-EINT8, 11 PK9/MCSIA-D3P/MCSI2-MCLK/UART4-CTS/UART2-RX/NCSI1-D10/JTAG-MAS-SRST/PK-EINT9, 12 PK6/MCSIA-D2N/TWI2-SCK/UART4-TX/UART2-RTS/SPI3-MOSI/NCSI1-D13/JTAG-MAS-DO/PK-EINT6, 13 PK7/MCSIA-D2P/TWI2-SDA/UART4-RX/UART2-CTS/SPI3-MISO/NCSI1-D12/JTAG-MAS-DI/PK-EINT7, 14 PK2/MCSIA-D1N/UART6-DTR/I2S4-LRCK/HDMI-SDA/TWI5-SDA/NCSI1-PCLK/SGPIO-SDATAIN/PK-EINT2, 15 PK3/MCSIA-D1P/UART6-RI/I2S4-DIN0/I2S4-DOUT1/TWI5-SCK/NCSI1-MCLK/SGPIO-SDATAOUT/PK-EINT3, 16 PK0/MCSIA-D0N/UART6-DCD/I2S4-BCLK/HDMI-CEC/TWI1-SDA/NCSI1-HSYNC/SGPIO-SLOAD/PK-EINT0, 17 PK1/MCSIA-D0P/UART6-DSR/I2S4-MCLK/HDMI-SCL/TWI1-SCK/NCSI1-VSYNC/SGPIO-SCLK/PK-EINT1, 18 PK4/MCSIA-CKN/PCIE-WAKEN/I2S4-DOUT0/I2S4-DIN1/SPI3-CS0/NCSI1-D15/JTAG-MAS-MS/PK-EINT4, 19 PK5/MCSIA-CKP/PCIE-CLKREQN/PWM1-8/PWM1-9/SPI3-CLK/NCSI1-D14/JTAG-MAS-CK/PK-EINT5, 20 PK22/MCSIC-D1N/TWI3-SCK/UART3-RTS/PWM1-6/NCSI1-HSYNC/UART1-TX/PK-EINT22, 21 PK23/MCSIC-D1P/TWI3-SDA/UART3-CTS/PWM1-7/NCSI1-VSYNC/UART1-RX/PK-EINT23, 22 PK20/MCSIC-D0N/TWI2-SCK/UART3-TX/PWM0-1/NCSI1-PCLK/UART1-RTS/PK-EINT20, 23 PK21/MCSIC-D0P/TWI2-SDA/UART3-RX/PWM0-2/NCSI1-MCLK/UART1-CTS/PK-EINT21, 24 PK24/MCSIC-CKN/MCSI0-MCLK/PWM0-6/TWI12-SCK/TWI10-SDA/PK-EINT24, 25 PK25/MCSIC-CKP/MCSI1-MCLK/PWM0-7/TWI12-SDA/TWI10-SCK/PK-EINT25, 26 PE0/MCSI0-MCLK/CSI0-XHS/SPI3-CS0/LPC-LAD0/NCSI0-HSYNC/UART6-TX/PE-EINT0, 27 PE9/MCSI2-MCLK/TCON-FSYNC0/I2S3-MCLK/LPC-LRESET/NCSI0-D5/UART6-RI/PE-EINT9, 28 PE6/CLK-FANOUT1/HDMI-CEC/I2S3-DIN0/I2S3-DOUT1/LPC-SERIRQ/NCSI0-D2/UART6-DTR/PE-EINT6, 29 PE7/CLK-FANOUT2/HDMI-SCL/I2S3-BCLK/LPC-LAD1/NCSI0-D3/TWI11-SCK/PE-EINT7, 30 PE8/CLK-FANOUT3/HDMI-SDA/I2S3-LRCK/LPC-LAD2/NCSI0-D4/TWI11-SDA/PE-EINT8, 31 PE10/TWI4-SCK/TCON-FSYNC1/I2S3-DIN3/I2S3-DOUT3/LPC-LAD3/NCSI0-D6/UART1-RTS/PE-EINT10, 32 PE1/TWI2-SCK/CSI1-XHS/SPI3-CLK/LPC-LPME/NCSI0-VSYNC/UART6-RX/PE-EINT1, 33 PE2/TWI2-SDA/CSI0-XVS-FSYNC/SPI3-MOSI/LPC-LPCPD/NCSI0-PCLK/UART6-RTS/PE-EINT2, 34 AFVCC-CSI, 35 DVDD-CSI, 36 AVDD-CSI, 37 IOVDD-CSI, 38 GND, 39 HCEC, 40 HHPD, 41 HSDA, 42 HSCL, 43 HTXCN, 44 HTXCP, 45 HTX0N, 46 HTX0P, 47 HTX1N, 48 HTX1P, 49 HTX2N, 50 HTX2P, 51 PD0/LCD0-D2/LVDS0-D0P/DSI0-D0P/EINK-D0/PWM0-0/PD-EINT0, 52 PD1/LCD0-D3/LVDS0-D0N/DSI0-D0N/EINK-D1/PWM0-1/PD-EINT1, 53 PD2/LCD0-D4/LVDS0-D1P/DSI0-D1P/EINK-D2/PWM0-2/PD-EINT2, 54 PD3/LCD0-D5/LVDS0-D1N/DSI0-D1N/EINK-D3/PWM0-3/PD-EINT3, 55 PD4/LCD0-D6/LVDS0-D2P/DSI0-CKP/EINK-D4/PWM0-4/PD-EINT4, 56 PD5/LCD0-D7/LVDS0-D2N/DSI0-CKN/EINK-D5/PWM0-5/PD-EINT5, 57 PD6/LCD0-D10/LVDS0-CKP/DSI0-D2P/EINK-D6/PWM0-6/PD-EINT6, 58 PD7/LCD0-D11/LVDS0-CKN/DSI0-D2N/EINK-D7/PWM0-7/PD-EINT7, 59 PD8/LCD0-D12/LVDS0-D3P/DSI0-D3P/EINK-D8/PWM0-8/PD-EINT8, 60 PD9/LCD0-D13/LVDS0-D3N/DSI0-D3N/EINK-D9/PWM0-9/PD-EINT9, 61 PD10/LCD0-D14/LVDS1-D0P/DSI1-D0P/EINK-D10/SPI1-CS0<DBI-CSX>/PWM1-0/PD-EINT10, 62 PD11/LCD0-D15/LVDS1-D0N/DSI1-D0N/EINK-D11/SPI1-CLK<DBI-SCLK>/PWM1-1/PD-EINT11, 63 PD12/LCD0-D18/LVDS1-D1P/DSI1-D1P/EINK-D12/SPI1-MOSI<DBI-SDO>/PWM1-2/PD-EINT12, 64 PD13/LCD0-D19/LVDS1-D1N/DSI1-D1N/EINK-D13/SPI1-MISO<DBI-SDI/DBI-TE/DBI-DCX>/PWM1-3/PD-EINT13, 65 PD14/LCD0-D20/LVDS1-D2P/DSI1-CKP/EINK-D14/SPI1-HOLD<DBI-DCX/DBI-WRX>/UART3-RTS/PD-EINT14, 66 PD15/LCD0-D21/LVDS1-D2N/DSI1-CKN/EINK-D15/SPI1-CS1/UART3-CTS/PD-EINT15, 67 PD16/LCD0-D22/LVDS1-CKP/DSI1-D2P/EINK-OEH/TWI2-SCK/UART3-TX/PD-EINT16, 68 PD17/LCD0-D23/LVDS1-CKN/DSI1-D2N/EINK-LEH/TWI2-SDA/UART3-RX/PD-EINT17, 69 PD18/LCD0-CLK/LVDS1-D3P/DSI1-D3P/EINK-CKH/SPI1-WP<DBI-TE>/UART4-RTS/PD-EINT18, 70 PD19/LCD0-DE/LVDS1-D3N/DSI1-D3N/EINK-STH/PWM1-5/UART4-CTS/PD-EINT19, 71 PF6/PF-EINT6, 72 PF0/SDC0-D1/JTAG-MS/TRACE-DATA3/UART5-RTS/TWI2-SCK/PF-EINT0, 73 PF3/SDC0-D0/JTAG-DI/TRACE-DATA0/UART5-CTS/TWI2-SDA/PF-EINT3, 74 PF2/SDC0-CLK/UART0-TX/TRACE-CLK/PF-EINT2, 75 PF1/SDC0-CMD/JTAG-DO/TRACE-DATA2/PF-EINT1, 76 PF4/SDC0-D3/UART0-RX/UART5-RX/PF-EINT4, 77 PF5/SDC0-D2/JTAG-CK/TRACE-DATA1/UART5-TX/PF-EINT5, 78 PD20/LCD0-HSYNC/DSI-TRIG-LCD-TE1/TWI0-SCK/EINK-CKV /PCIE-CLKREQN/UART4-TX/TWI3-SCK/PWM0-2/PD-EINT20, 79 PD21/LCD0-VSYNC/TWI0-SDA/EINK-MODE/PCIE-WAKEN/UART4-RX/TWI3-SDA/PWM0-3/PD-EINT21, 80 PD22/PWM0-4/EINK-STV/PCIE-PERSTN/TWI0-SCK/TWI2-SCK/PWM1-4/PD-EINT22, 81 PD23/PWM0-5/PCIE-CLKREQN/TWI0-SDA/TWI2-SDA/PWM1-5/PD-EINT23, 82 PH15/UART5-RTS/LEDC/DSI-TRIG-LCD-TE1/RGMII0-EPHY-25/50M/PH-EINT15, 83 PH3/TWI1-SDA/I2S2-BCLK/RGMII0-CLKIN/RMII0-RXER/SPI1-MISO/PH-EINT3, 84 PH12/DMIC-DATA3/SPI2-CS1/RGMII0-RXCK/RMII0-NULL/PH-EINT12, 85 PH2/TWI1-SCK/I2S2-MCLK/RGMII0-RXCTL/RMII0-CRS-DV/SPI1-CS1/PH-EINT2, 86 PH1/TWI0-SDA/I2S2-DOUT3/I2S2-DIN3/RGMII0-RXD0/RMII0-RXD0/TWI3-SDA/SPI1-WP/PH-EINT1, 87 PH0/TWI0-SCK/I2S2-DOUT2/I2S2-DIN2/RGMII0-RXD1/RMII0-RXD1/TWI3-SCK/SPI1-HOLD/PH-EINT0, 88 PH11/DMIC-DATA2/SPI2-MISO/RGMII0-RXD2/RMII0-NULL/PH-EINT11, 89 PH10/DMIC-DATA1/SPI2-MOSI/RGMII0-RXD3/RMII0-NULL/PH-EINT10, 90 PH6/UART3-RTS/I2S2-DOUT1/I2S2-DIN0/RGMII0-TXCK/RMII0-TXCK/SPI1-CLK/PH-EINT6, 91 PH7/UART3-CTS/SPI2-CS2/DSI-TRIG-LCD-TE1/RGMII0-TXCTL/RMII0-TXEN/PH-EINT7, 92 PH5/UART3-RX/I2S2-DIN1/I2S2-DOUT0/RGMII0-TXD0/RMII0-TXD0/SPI1-MOSI/PH-EINT5, 93 PH4/UART3-TX/SPI2-CS3/I2S2-LRCK/RGMII0-TXD1/RMII0-TXD1/SPI1-CS0/PH-EINT4, 94 PH14/UART5-RX/RGMII0-TXD2/RMII0-NULL/TWI7-SCK/PH-EINT14, 95 GND, 96 PH13/UART5-TX/RGMII0-TXD3/RMII0-NULL/TWI7-SDA/PH-EINT13, 97 PH9/DMIC-DATA0/SPI2-CS0/RGMII0-MDIO/PH-EINT9, 98 PH8/DMIC-CLK/SPI2-CLK/RGMII0-MDC/PH-EINT8, 99 PH16/UART5-CTS/IR-TX/PH-EINT16, 100 PJ22/PWM1-4/UART3-TX/UART2-RTS/TWI7-SCK/TWI3-SCK/TWI11-SCK/LCD0-D8/PJ-EINT22, 101 PJ23/PWM1-5/UART3-RX/UART2-CTS/TWI7-SDA/TWI3-SDA/TWI11-SDA/LCD0-D9/PJ-EINT23, 102 PJ24/PWM1-6/UART4-TX/TWI4-SCK/SPI3-CLK/PJ-EINT24, 103 PJ25/PWM1-7/UART4-RX/TWI4-SDA/SPI3-MOSI/PJ-EINT25, 104 PJ26/PWM1-8/UART4-RTS/UART2-TX/TWI5-SCK/SPI3-MISO/LCD0-D16/PJ-EINT26, 105 PJ27/PWM1-9/UART4-CTS/UART2-RX/DSI-TRIG-LCD-TE1/TWI5-SDA/SPI3-CS0/LCD0-D17/PJ-EINT27, 106 PB0/UART2-TX/UART0-TX/SPI2-CS0/DSI-TRIG-LCD-TE1/LCD0-D0/JTAG-MS/PB-EINT0, 107 PB1/UART2-RX/UART0-RX/SPI2-CLK/LCD0-D1/JTAG-CK/PB-EINT1, 108 PB2/UART2-RTS/SPI2-MOSI/HDMI-SCL/LCD0-D8/JTAG-DO/TWI0-SCK/PB-EINT2, 109 PB3/UART2-CTS/SPI2-MISO/HDMI-SDA/LCD0-D9/JTAG-DI/TWI0-SDA/PB-EINT3, 110 PB4/PWM0-0/I2S0-MCLK/SPI2-CS1/HDMI-CEC/LCD0-D16/TRACE-CLK/TWI1-SCK/PB-EINT4, 111 PB5/I2S0-BCLK/SPI2-CS2/PWM0-1/LCD0-D17/TRACE-DATA0/TWI1-SDA/PB-EINT5, 112 PB6/CLK-FANOUT1/I2S0-LRCK/SPI2-CS3/PWM0-2/PWM0-8/TRACE-DATA1/PB-EINT6, 113 PB7/CLK-FANOUT2/I2S0-DOUT0/I2S0-DIN1/PWM0-9/OWA0-IN/TRACE-DATA2/TWI1-SCK/PB-EINT7, 114 PB8/CLK-FANOUT3/I2S0-DIN0/I2S0-DOUT1/PWM1-0/OWA0-OUT/TRACE-DATA3/TWI1-SDA/PB-EINT8, 115 PB9/UART0-TX/I2S0-DIN2/I2S0-DOUT2/PWM1-1/WATCHDOG-SIG/LCD0-D16/TWI8-SCK/TWI0-SCK/PB-EINT9, 116 PB10/UART0-RX/I2S0-DIN3/I2S0-DOUT3/PWM1-2/PLL-LOCK-DBG/LCD0-D17/TWI8-SDA/TWI0-SDA/PB-EINT10, 117 USB0-DM, 118 USB0-DP, 119 USB1-DM, 120 USB1-DP, 121 PCIE1-TX0P/USB2-U3-TX0P, 122 PCIE1-TX0N/USB2-U3-TX0N, 123 USB2-DM, 124 USB2-DP, 125 PCIE1-RX0P/USB2-U3-RX0P, 126 PCIE1-RX0N/USB2-U3-RX0N, 127 COMB1-REF-CLKP, 128 COMB1-REF-CLKN, 129 PE11/TWI4-SDA/SPI3-MISO/I2S3-DIN2/I2S3-DOUT2/PCIE-CLKREQN/NCSI0-D7/UART1-CTS/PE-EINT11, 130 PE14/SPI3-MOSI/PWM1-8/PCIE-CLKREQN/IR-RX/TWI9-SCK/PE-EINT14, 131 PE12/SPI3-CS0/I2S3-DOUT0/I2S3-DIN1/PCIE-WAKEN/UART1-TX/PE-EINT12, 132 PE13/SPI3-CLK/PCIE-PERSTN/UART1-RX/PE-EINT13, 133 PE15/SPI3-CS1/PWM1-9/IR-RX/TWI9-SDA/PE-EINT15, 134 DP-HPD, 135 DP-AUXN, 136 DP-AUXP, 137 TYPEC-TX1P/U3-TX0P/DP/EDP-TX0P, 138 TYPEC-TX1N/U3-TX0N/DP/EDP-TX0N, 139 TYPEC-RX1P/U3-RX0N/DP/EDP-TX1P, 140 TYPEC-RX1N/U3-RX0P/DP/EDP-TX1N, 141 TYPEC-RX2P/U3-RX0P/DP/EDP-TX2P, 142 TYPEC-RX2N/U3-RX0N/DP/EDP-TX2N, 143 TYPEC-TX2P/U3-TX0P/DP/EDP-TX3P, 144 TYPEC-TX2N/U3-TX0N/DP/EDP-TX3N, 145 FEL, 146 PC7/NAND-RB1/SPI0-CS1/SPIF0-DQS/PC-EINT7, 147 PC3/NAND-CE1/SPI0-CS0/SPIF0-CS0/PC-EINT3, 148 PC4/NAND-CE0/SPI0-MISO/SPIF0-MISO/PC-EINT4, 149 PC2/NAND-CLE/SPI0-MOSI/SPIF0-MOSI/PC-EINT2, 150 PC12/NAND-DQS/SPI0-CLK/SPIF0-CLK/PC-EINT12, 151 VCC-RTC, 152 GND, 153 BAT, 154 BAT, 155 TS, 156 CHGLED, 157 PSOUT, 158 PSOUT, 159 PMU-SDA, 160 PMU-SCK, 161 RESET, 162 PWRON, 163 PMU-IRQ, 164 VMID, 165 5V-IN, 166 5V-IN, 167 GND, 168 GND, 169 PM5/S-UART0-RX/S-TWI2-SDA/S-TWI1-SDA/S-UART1-RX/S-PWM0-1/S-IR-RX/PM-EINT5, 170 PL13/S-UART1-RX/S-TWI1-SDA/S-TWI2-SDA/PL-EINT13, 171 PL12/S-UART1-TX/S-TWI1-SCK/S-TWI2-SCK/S-IR-RX/PL-EINT12, 172 PL2/S-UART1-TX/S-UART0-TX/S-TWI1-SDA/S-PWM0-0/PL-EINT2, 173 PL3/S-UART1-RX/S-UART0-RX/S-TWI1-SCK/S-IR-RX/S-PWM0-1/PL-EINT3, 174 PL4/S-JTAG-MS/S-TWI2-SCK/S-SPI0-CS0/S-IR-RX/S-PWM0-2/PL-EINT4, 175 PL5/S-JTAG-CK/S-TWI2-SDA/S-SPI0-CLK/S-PWM0-3/PL-EINT5, 176 PL6/S-JTAG-DO/S-UART0-TX/S-SPI0-MOSI/S-IR-RX/S-PWM0-4/PL-EINT6, 177 PL7/S-JTAG-DI/S-UART0-RX/S-SPI0-MISO/S-PWM0-5/PL-EINT7, 178 PL8/S-TWI1-SCK/S-UART1-TX/S-TWI0-SCK/S-TWI2-SCK/S-PWM0-6/PL-EINT8, 179 PL9/S-TWI1-SDA/S-UART1-RX/S-TWI0-SDA/S-TWI2-SDA/S-PWM0-7/PL-EINT9, 180 PL10/S-UART0-TX/S-TWI2-SCK/S-UART1-TX/S-PWM0-8/PL-EINT10, 181 PL11/S-UART0-RX/S-TWI2-SDA/S-UART1-RX/S-IR-RX/S-PWM0-9/PL-EINT11, 182 AVCC, 183 LRADC0, 184 PK12/MCSIB-D1N/UART6-RTS/PWM0-5/NCSI1-D7/PK-EINT12, 185 PK13/MCSIB-D1P/UART6-CTS/PWM0-6/NCSI1-D6/PK-EINT13, 186 PK10/MCSIB-D0N/UART6-TX/PWM0-3/NCSI1-D9/PK-EINT10, 187 PK11/MCSIB-D0P/UART6-RX/PWM0-4/NCSI1-D8/PK-EINT11, 188 GND, 189 NC, 190 GPADC4, 191 GPADC5, 192 GPADC6, 193 PC1/NAND-ALE/SDC2-RST/SDC3-RST/PC-EINT1, 194 PC0/NAND-WE/SDC2-DS/SDC3-DS/PC-EINT0, 195 PC5/NAND-RE/SDC2-CLK/SDC3-CLK/PC-EINT5, 196 PC6/NAND-RB0/SDC2-CMD/SDC3-CMD/PC-EINT6, 197 PC8/NAND-DQ7/SDC2-D3/SDC3-D3/SPIF0-D7/PC-EINT8, 198 PC9/NAND-DQ6/SDC2-D4/SDC3-D4/SPIF0-D6/PC-EINT9, 199 PC10/NAND-DQ5/SDC2-D0/SDC3-D0/SPIF0-D5/PC-EINT10, 200 PC11/NAND-DQ4/SDC2-D5/SDC3-D5/SPIF0-D4/PC-EINT11, 201 PC13/NAND-DQ3/SDC2-D1/SDC3-D1/PC-EINT13, 202 PC14/NAND-DQ2/SDC2-D6/SDC3-D6/PC-EINT14, 203 PC15/NAND-DQ1/SDC2-D2/SDC3-D2/SPI0-WP/SPIF0-WP/PC-EINT15, 204 PC16/NAND-DQ0/SDC2-D7/SDC3-D7/SPI0-HOLD/SPIF0-HOLD/PC-EINT16

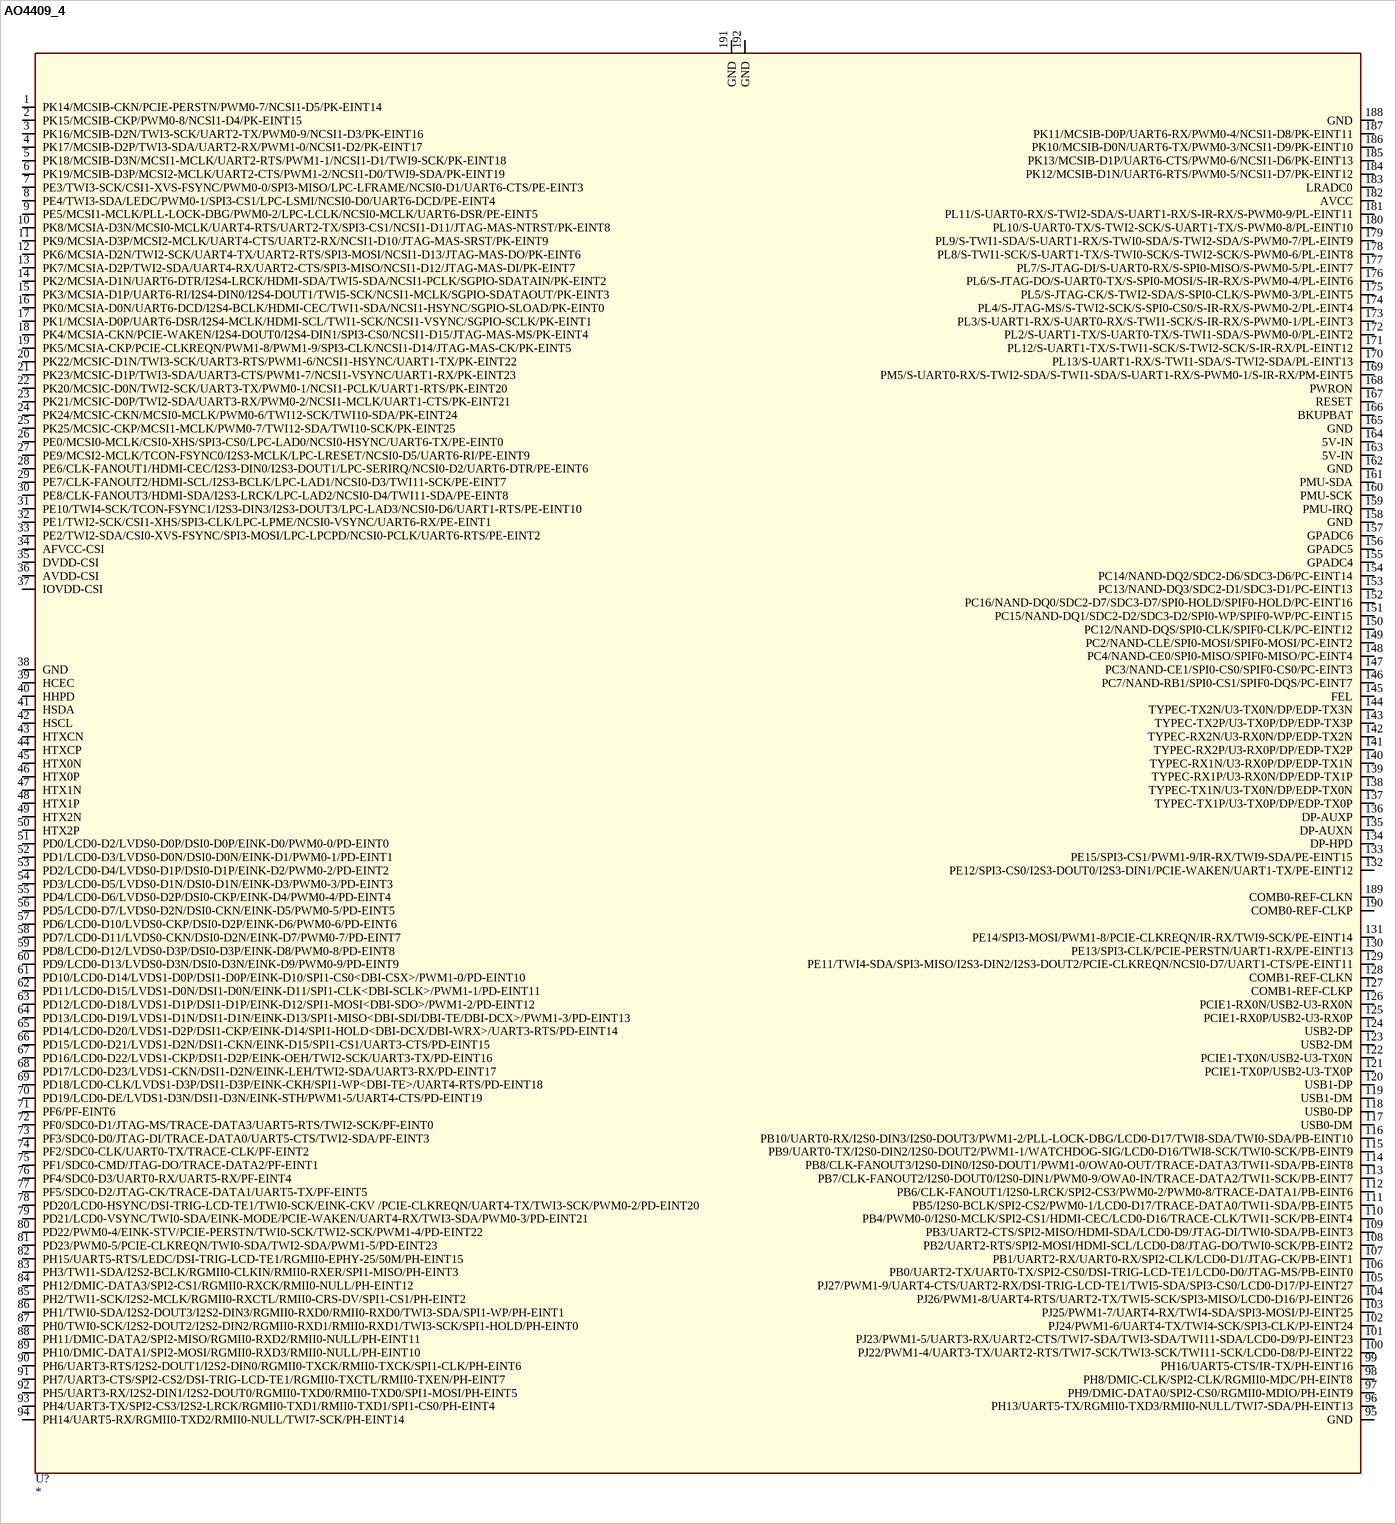
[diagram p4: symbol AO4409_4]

## AO4409_4
designator U?
pins: 1 PK14/MCSIB-CKN/PCIE-PERSTN/PWM0-7/NCSI1-D5/PK-EINT14, 2 PK15/MCSIB-CKP/PWM0-8/NCSI1-D4/PK-EINT15, 3 PK16/MCSIB-D2N/TWI3-SCK/UART2-TX/PWM0-9/NCSI1-D3/PK-EINT16, 4 PK17/MCSIB-D2P/TWI3-SDA/UART2-RX/PWM1-0/NCSI1-D2/PK-EINT17, 5 PK18/MCSIB-D3N/MCSI1-MCLK/UART2-RTS/PWM1-1/NCSI1-D1/TWI9-SCK/PK-EINT18, 6 PK19/MCSIB-D3P/MCSI2-MCLK/UART2-CTS/PWM1-2/NCSI1-D0/TWI9-SDA/PK-EINT19, 7 PE3/TWI3-SCK/CSI1-XVS-FSYNC/PWM0-0/SPI3-MISO/LPC-LFRAME/NCSI0-D1/UART6-CTS/PE-EINT3, 8 PE4/TWI3-SDA/LEDC/PWM0-1/SPI3-CS1/LPC-LSMI/NCSI0-D0/UART6-DCD/PE-EINT4, 9 PE5/MCSI1-MCLK/PLL-LOCK-DBG/PWM0-2/LPC-LCLK/NCSI0-MCLK/UART6-DSR/PE-EINT5, 10 PK8/MCSIA-D3N/MCSI0-MCLK/UART4-RTS/UART2-TX/SPI3-CS1/NCSI1-D11/JTAG-MAS-NTRST/PK-EINT8, 11 PK9/MCSIA-D3P/MCSI2-MCLK/UART4-CTS/UART2-RX/NCSI1-D10/JTAG-MAS-SRST/PK-EINT9, 12 PK6/MCSIA-D2N/TWI2-SCK/UART4-TX/UART2-RTS/SPI3-MOSI/NCSI1-D13/JTAG-MAS-DO/PK-EINT6, 13 PK7/MCSIA-D2P/TWI2-SDA/UART4-RX/UART2-CTS/SPI3-MISO/NCSI1-D12/JTAG-MAS-DI/PK-EINT7, 14 PK2/MCSIA-D1N/UART6-DTR/I2S4-LRCK/HDMI-SDA/TWI5-SDA/NCSI1-PCLK/SGPIO-SDATAIN/PK-EINT2, 15 PK3/MCSIA-D1P/UART6-RI/I2S4-DIN0/I2S4-DOUT1/TWI5-SCK/NCSI1-MCLK/SGPIO-SDATAOUT/PK-EINT3, 16 PK0/MCSIA-D0N/UART6-DCD/I2S4-BCLK/HDMI-CEC/TWI1-SDA/NCSI1-HSYNC/SGPIO-SLOAD/PK-EINT0, 17 PK1/MCSIA-D0P/UART6-DSR/I2S4-MCLK/HDMI-SCL/TWI1-SCK/NCSI1-VSYNC/SGPIO-SCLK/PK-EINT1, 18 PK4/MCSIA-CKN/PCIE-WAKEN/I2S4-DOUT0/I2S4-DIN1/SPI3-CS0/NCSI1-D15/JTAG-MAS-MS/PK-EINT4, 19 PK5/MCSIA-CKP/PCIE-CLKREQN/PWM1-8/PWM1-9/SPI3-CLK/NCSI1-D14/JTAG-MAS-CK/PK-EINT5, 20 PK22/MCSIC-D1N/TWI3-SCK/UART3-RTS/PWM1-6/NCSI1-HSYNC/UART1-TX/PK-EINT22, 21 PK23/MCSIC-D1P/TWI3-SDA/UART3-CTS/PWM1-7/NCSI1-VSYNC/UART1-RX/PK-EINT23, 22 PK20/MCSIC-D0N/TWI2-SCK/UART3-TX/PWM0-1/NCSI1-PCLK/UART1-RTS/PK-EINT20, 23 PK21/MCSIC-D0P/TWI2-SDA/UART3-RX/PWM0-2/NCSI1-MCLK/UART1-CTS/PK-EINT21, 24 PK24/MCSIC-CKN/MCSI0-MCLK/PWM0-6/TWI12-SCK/TWI10-SDA/PK-EINT24, 25 PK25/MCSIC-CKP/MCSI1-MCLK/PWM0-7/TWI12-SDA/TWI10-SCK/PK-EINT25, 26 PE0/MCSI0-MCLK/CSI0-XHS/SPI3-CS0/LPC-LAD0/NCSI0-HSYNC/UART6-TX/PE-EINT0, 27 PE9/MCSI2-MCLK/TCON-FSYNC0/I2S3-MCLK/LPC-LRESET/NCSI0-D5/UART6-RI/PE-EINT9, 28 PE6/CLK-FANOUT1/HDMI-CEC/I2S3-DIN0/I2S3-DOUT1/LPC-SERIRQ/NCSI0-D2/UART6-DTR/PE-EINT6, 29 PE7/CLK-FANOUT2/HDMI-SCL/I2S3-BCLK/LPC-LAD1/NCSI0-D3/TWI11-SCK/PE-EINT7, 30 PE8/CLK-FANOUT3/HDMI-SDA/I2S3-LRCK/LPC-LAD2/NCSI0-D4/TWI11-SDA/PE-EINT8, 31 PE10/TWI4-SCK/TCON-FSYNC1/I2S3-DIN3/I2S3-DOUT3/LPC-LAD3/NCSI0-D6/UART1-RTS/PE-EINT10, 32 PE1/TWI2-SCK/CSI1-XHS/SPI3-CLK/LPC-LPME/NCSI0-VSYNC/UART6-RX/PE-EINT1, 33 PE2/TWI2-SDA/CSI0-XVS-FSYNC/SPI3-MOSI/LPC-LPCPD/NCSI0-PCLK/UART6-RTS/PE-EINT2, 34 AFVCC-CSI, 35 DVDD-CSI, 36 AVDD-CSI, 37 IOVDD-CSI, 38 GND, 39 HCEC, 40 HHPD, 41 HSDA, 42 HSCL, 43 HTXCN, 44 HTXCP, 45 HTX0N, 46 HTX0P, 47 HTX1N, 48 HTX1P, 49 HTX2N, 50 HTX2P, 51 PD0/LCD0-D2/LVDS0-D0P/DSI0-D0P/EINK-D0/PWM0-0/PD-EINT0, 52 PD1/LCD0-D3/LVDS0-D0N/DSI0-D0N/EINK-D1/PWM0-1/PD-EINT1, 53 PD2/LCD0-D4/LVDS0-D1P/DSI0-D1P/EINK-D2/PWM0-2/PD-EINT2, 54 PD3/LCD0-D5/LVDS0-D1N/DSI0-D1N/EINK-D3/PWM0-3/PD-EINT3, 55 PD4/LCD0-D6/LVDS0-D2P/DSI0-CKP/EINK-D4/PWM0-4/PD-EINT4, 56 PD5/LCD0-D7/LVDS0-D2N/DSI0-CKN/EINK-D5/PWM0-5/PD-EINT5, 57 PD6/LCD0-D10/LVDS0-CKP/DSI0-D2P/EINK-D6/PWM0-6/PD-EINT6, 58 PD7/LCD0-D11/LVDS0-CKN/DSI0-D2N/EINK-D7/PWM0-7/PD-EINT7, 59 PD8/LCD0-D12/LVDS0-D3P/DSI0-D3P/EINK-D8/PWM0-8/PD-EINT8, 60 PD9/LCD0-D13/LVDS0-D3N/DSI0-D3N/EINK-D9/PWM0-9/PD-EINT9, 61 PD10/LCD0-D14/LVDS1-D0P/DSI1-D0P/EINK-D10/SPI1-CS0<DBI-CSX>/PWM1-0/PD-EINT10, 62 PD11/LCD0-D15/LVDS1-D0N/DSI1-D0N/EINK-D11/SPI1-CLK<DBI-SCLK>/PWM1-1/PD-EINT11, 63 PD12/LCD0-D18/LVDS1-D1P/DSI1-D1P/EINK-D12/SPI1-MOSI<DBI-SDO>/PWM1-2/PD-EINT12, 64 PD13/LCD0-D19/LVDS1-D1N/DSI1-D1N/EINK-D13/SPI1-MISO<DBI-SDI/DBI-TE/DBI-DCX>/PWM1-3/PD-EINT13, 65 PD14/LCD0-D20/LVDS1-D2P/DSI1-CKP/EINK-D14/SPI1-HOLD<DBI-DCX/DBI-WRX>/UART3-RTS/PD-EINT14, 66 PD15/LCD0-D21/LVDS1-D2N/DSI1-CKN/EINK-D15/SPI1-CS1/UART3-CTS/PD-EINT15, 67 PD16/LCD0-D22/LVDS1-CKP/DSI1-D2P/EINK-OEH/TWI2-SCK/UART3-TX/PD-EINT16, 68 PD17/LCD0-D23/LVDS1-CKN/DSI1-D2N/EINK-LEH/TWI2-SDA/UART3-RX/PD-EINT17, 69 PD18/LCD0-CLK/LVDS1-D3P/DSI1-D3P/EINK-CKH/SPI1-WP<DBI-TE>/UART4-RTS/PD-EINT18, 70 PD19/LCD0-DE/LVDS1-D3N/DSI1-D3N/EINK-STH/PWM1-5/UART4-CTS/PD-EINT19, 71 PF6/PF-EINT6, 72 PF0/SDC0-D1/JTAG-MS/TRACE-DATA3/UART5-RTS/TWI2-SCK/PF-EINT0, 73 PF3/SDC0-D0/JTAG-DI/TRACE-DATA0/UART5-CTS/TWI2-SDA/PF-EINT3, 74 PF2/SDC0-CLK/UART0-TX/TRACE-CLK/PF-EINT2, 75 PF1/SDC0-CMD/JTAG-DO/TRACE-DATA2/PF-EINT1, 76 PF4/SDC0-D3/UART0-RX/UART5-RX/PF-EINT4, 77 PF5/SDC0-D2/JTAG-CK/TRACE-DATA1/UART5-TX/PF-EINT5, 78 PD20/LCD0-HSYNC/DSI-TRIG-LCD-TE1/TWI0-SCK/EINK-CKV /PCIE-CLKREQN/UART4-TX/TWI3-SCK/PWM0-2/PD-EINT20, 79 PD21/LCD0-VSYNC/TWI0-SDA/EINK-MODE/PCIE-WAKEN/UART4-RX/TWI3-SDA/PWM0-3/PD-EINT21, 80 PD22/PWM0-4/EINK-STV/PCIE-PERSTN/TWI0-SCK/TWI2-SCK/PWM1-4/PD-EINT22, 81 PD23/PWM0-5/PCIE-CLKREQN/TWI0-SDA/TWI2-SDA/PWM1-5/PD-EINT23, 82 PH15/UART5-RTS/LEDC/DSI-TRIG-LCD-TE1/RGMII0-EPHY-25/50M/PH-EINT15, 83 PH3/TWI1-SDA/I2S2-BCLK/RGMII0-CLKIN/RMII0-RXER/SPI1-MISO/PH-EINT3, 84 PH12/DMIC-DATA3/SPI2-CS1/RGMII0-RXCK/RMII0-NULL/PH-EINT12, 85 PH2/TWI1-SCK/I2S2-MCLK/RGMII0-RXCTL/RMII0-CRS-DV/SPI1-CS1/PH-EINT2, 86 PH1/TWI0-SDA/I2S2-DOUT3/I2S2-DIN3/RGMII0-RXD0/RMII0-RXD0/TWI3-SDA/SPI1-WP/PH-EINT1, 87 PH0/TWI0-SCK/I2S2-DOUT2/I2S2-DIN2/RGMII0-RXD1/RMII0-RXD1/TWI3-SCK/SPI1-HOLD/PH-EINT0, 88 PH11/DMIC-DATA2/SPI2-MISO/RGMII0-RXD2/RMII0-NULL/PH-EINT11, 89 PH10/DMIC-DATA1/SPI2-MOSI/RGMII0-RXD3/RMII0-NULL/PH-EINT10, 90 PH6/UART3-RTS/I2S2-DOUT1/I2S2-DIN0/RGMII0-TXCK/RMII0-TXCK/SPI1-CLK/PH-EINT6, 91 PH7/UART3-CTS/SPI2-CS2/DSI-TRIG-LCD-TE1/RGMII0-TXCTL/RMII0-TXEN/PH-EINT7, 92 PH5/UART3-RX/I2S2-DIN1/I2S2-DOUT0/RGMII0-TXD0/RMII0-TXD0/SPI1-MOSI/PH-EINT5, 93 PH4/UART3-TX/SPI2-CS3/I2S2-LRCK/RGMII0-TXD1/RMII0-TXD1/SPI1-CS0/PH-EINT4, 94 PH14/UART5-RX/RGMII0-TXD2/RMII0-NULL/TWI7-SCK/PH-EINT14, 95 GND, 96 PH13/UART5-TX/RGMII0-TXD3/RMII0-NULL/TWI7-SDA/PH-EINT13, 97 PH9/DMIC-DATA0/SPI2-CS0/RGMII0-MDIO/PH-EINT9, 98 PH8/DMIC-CLK/SPI2-CLK/RGMII0-MDC/PH-EINT8, 99 PH16/UART5-CTS/IR-TX/PH-EINT16, 100 PJ22/PWM1-4/UART3-TX/UART2-RTS/TWI7-SCK/TWI3-SCK/TWI11-SCK/LCD0-D8/PJ-EINT22, 101 PJ23/PWM1-5/UART3-RX/UART2-CTS/TWI7-SDA/TWI3-SDA/TWI11-SDA/LCD0-D9/PJ-EINT23, 102 PJ24/PWM1-6/UART4-TX/TWI4-SCK/SPI3-CLK/PJ-EINT24, 103 PJ25/PWM1-7/UART4-RX/TWI4-SDA/SPI3-MOSI/PJ-EINT25, 104 PJ26/PWM1-8/UART4-RTS/UART2-TX/TWI5-SCK/SPI3-MISO/LCD0-D16/PJ-EINT26, 105 PJ27/PWM1-9/UART4-CTS/UART2-RX/DSI-TRIG-LCD-TE1/TWI5-SDA/SPI3-CS0/LCD0-D17/PJ-EINT27, 106 PB0/UART2-TX/UART0-TX/SPI2-CS0/DSI-TRIG-LCD-TE1/LCD0-D0/JTAG-MS/PB-EINT0, 107 PB1/UART2-RX/UART0-RX/SPI2-CLK/LCD0-D1/JTAG-CK/PB-EINT1, 108 PB2/UART2-RTS/SPI2-MOSI/HDMI-SCL/LCD0-D8/JTAG-DO/TWI0-SCK/PB-EINT2, 109 PB3/UART2-CTS/SPI2-MISO/HDMI-SDA/LCD0-D9/JTAG-DI/TWI0-SDA/PB-EINT3, 110 PB4/PWM0-0/I2S0-MCLK/SPI2-CS1/HDMI-CEC/LCD0-D16/TRACE-CLK/TWI1-SCK/PB-EINT4, 111 PB5/I2S0-BCLK/SPI2-CS2/PWM0-1/LCD0-D17/TRACE-DATA0/TWI1-SDA/PB-EINT5, 112 PB6/CLK-FANOUT1/I2S0-LRCK/SPI2-CS3/PWM0-2/PWM0-8/TRACE-DATA1/PB-EINT6, 113 PB7/CLK-FANOUT2/I2S0-DOUT0/I2S0-DIN1/PWM0-9/OWA0-IN/TRACE-DATA2/TWI1-SCK/PB-EINT7, 114 PB8/CLK-FANOUT3/I2S0-DIN0/I2S0-DOUT1/PWM1-0/OWA0-OUT/TRACE-DATA3/TWI1-SDA/PB-EINT8, 115 PB9/UART0-TX/I2S0-DIN2/I2S0-DOUT2/PWM1-1/WATCHDOG-SIG/LCD0-D16/TWI8-SCK/TWI0-SCK/PB-EINT9, 116 PB10/UART0-RX/I2S0-DIN3/I2S0-DOUT3/PWM1-2/PLL-LOCK-DBG/LCD0-D17/TWI8-SDA/TWI0-SDA/PB-EINT10, 117 USB0-DM, 118 USB0-DP, 119 USB1-DM, 120 USB1-DP, 121 PCIE1-TX0P/USB2-U3-TX0P, 122 PCIE1-TX0N/USB2-U3-TX0N, 123 USB2-DM, 124 USB2-DP, 125 PCIE1-RX0P/USB2-U3-RX0P, 126 PCIE1-RX0N/USB2-U3-RX0N, 127 COMB1-REF-CLKP, 128 COMB1-REF-CLKN, 129 PE11/TWI4-SDA/SPI3-MISO/I2S3-DIN2/I2S3-DOUT2/PCIE-CLKREQN/NCSI0-D7/UART1-CTS/PE-EINT11, 130 PE13/SPI3-CLK/PCIE-PERSTN/UART1-RX/PE-EINT13, 131 PE14/SPI3-MOSI/PWM1-8/PCIE-CLKREQN/IR-RX/TWI9-SCK/PE-EINT14, 132 PE12/SPI3-CS0/I2S3-DOUT0/I2S3-DIN1/PCIE-WAKEN/UART1-TX/PE-EINT12, 133 PE15/SPI3-CS1/PWM1-9/IR-RX/TWI9-SDA/PE-EINT15, 134 DP-HPD, 135 DP-AUXN, 136 DP-AUXP, 137 TYPEC-TX1P/U3-TX0P/DP/EDP-TX0P, 138 TYPEC-TX1N/U3-TX0N/DP/EDP-TX0N, 139 TYPEC-RX1P/U3-RX0N/DP/EDP-TX1P, 140 TYPEC-RX1N/U3-RX0P/DP/EDP-TX1N, 141 TYPEC-RX2P/U3-RX0P/DP/EDP-TX2P, 142 TYPEC-RX2N/U3-RX0N/DP/EDP-TX2N, 143 TYPEC-TX2P/U3-TX0P/DP/EDP-TX3P, 144 TYPEC-TX2N/U3-TX0N/DP/EDP-TX3N, 145 FEL, 146 PC7/NAND-RB1/SPI0-CS1/SPIF0-DQS/PC-EINT7, 147 PC3/NAND-CE1/SPI0-CS0/SPIF0-CS0/PC-EINT3, 148 PC4/NAND-CE0/SPI0-MISO/SPIF0-MISO/PC-EINT4, 149 PC2/NAND-CLE/SPI0-MOSI/SPIF0-MOSI/PC-EINT2, 150 PC12/NAND-DQS/SPI0-CLK/SPIF0-CLK/PC-EINT12, 151 PC15/NAND-DQ1/SDC2-D2/SDC3-D2/SPI0-WP/SPIF0-WP/PC-EINT15, 152 PC16/NAND-DQ0/SDC2-D7/SDC3-D7/SPI0-HOLD/SPIF0-HOLD/PC-EINT16, 153 PC13/NAND-DQ3/SDC2-D1/SDC3-D1/PC-EINT13, 154 PC14/NAND-DQ2/SDC2-D6/SDC3-D6/PC-EINT14, 155 GPADC4, 156 GPADC5, 157 GPADC6, 158 GND, 159 PMU-IRQ, 160 PMU-SCK, 161 PMU-SDA, 162 GND, 163 5V-IN, 164 5V-IN, 165 GND, 166 BKUPBAT, 167 RESET, 168 PWRON, 169 PM5/S-UART0-RX/S-TWI2-SDA/S-TWI1-SDA/S-UART1-RX/S-PWM0-1/S-IR-RX/PM-EINT5, 170 PL13/S-UART1-RX/S-TWI1-SDA/S-TWI2-SDA/PL-EINT13, 171 PL12/S-UART1-TX/S-TWI1-SCK/S-TWI2-SCK/S-IR-RX/PL-EINT12, 172 PL2/S-UART1-TX/S-UART0-TX/S-TWI1-SDA/S-PWM0-0/PL-EINT2, 173 PL3/S-UART1-RX/S-UART0-RX/S-TWI1-SCK/S-IR-RX/S-PWM0-1/PL-EINT3, 174 PL4/S-JTAG-MS/S-TWI2-SCK/S-SPI0-CS0/S-IR-RX/S-PWM0-2/PL-EINT4, 175 PL5/S-JTAG-CK/S-TWI2-SDA/S-SPI0-CLK/S-PWM0-3/PL-EINT5, 176 PL6/S-JTAG-DO/S-UART0-TX/S-SPI0-MOSI/S-IR-RX/S-PWM0-4/PL-EINT6, 177 PL7/S-JTAG-DI/S-UART0-RX/S-SPI0-MISO/S-PWM0-5/PL-EINT7, 178 PL8/S-TWI1-SCK/S-UART1-TX/S-TWI0-SCK/S-TWI2-SCK/S-PWM0-6/PL-EINT8, 179 PL9/S-TWI1-SDA/S-UART1-RX/S-TWI0-SDA/S-TWI2-SDA/S-PWM0-7/PL-EINT9, 180 PL10/S-UART0-TX/S-TWI2-SCK/S-UART1-TX/S-PWM0-8/PL-EINT10, 181 PL11/S-UART0-RX/S-TWI2-SDA/S-UART1-RX/S-IR-RX/S-PWM0-9/PL-EINT11, 182 AVCC, 183 LRADC0, 184 PK12/MCSIB-D1N/UART6-RTS/PWM0-5/NCSI1-D7/PK-EINT12, 185 PK13/MCSIB-D1P/UART6-CTS/PWM0-6/NCSI1-D6/PK-EINT13, 186 PK10/MCSIB-D0N/UART6-TX/PWM0-3/NCSI1-D9/PK-EINT10, 187 PK11/MCSIB-D0P/UART6-RX/PWM0-4/NCSI1-D8/PK-EINT11, 188 GND, 189 COMB0-REF-CLKN, 190 COMB0-REF-CLKP, 191 GND, 192 GND

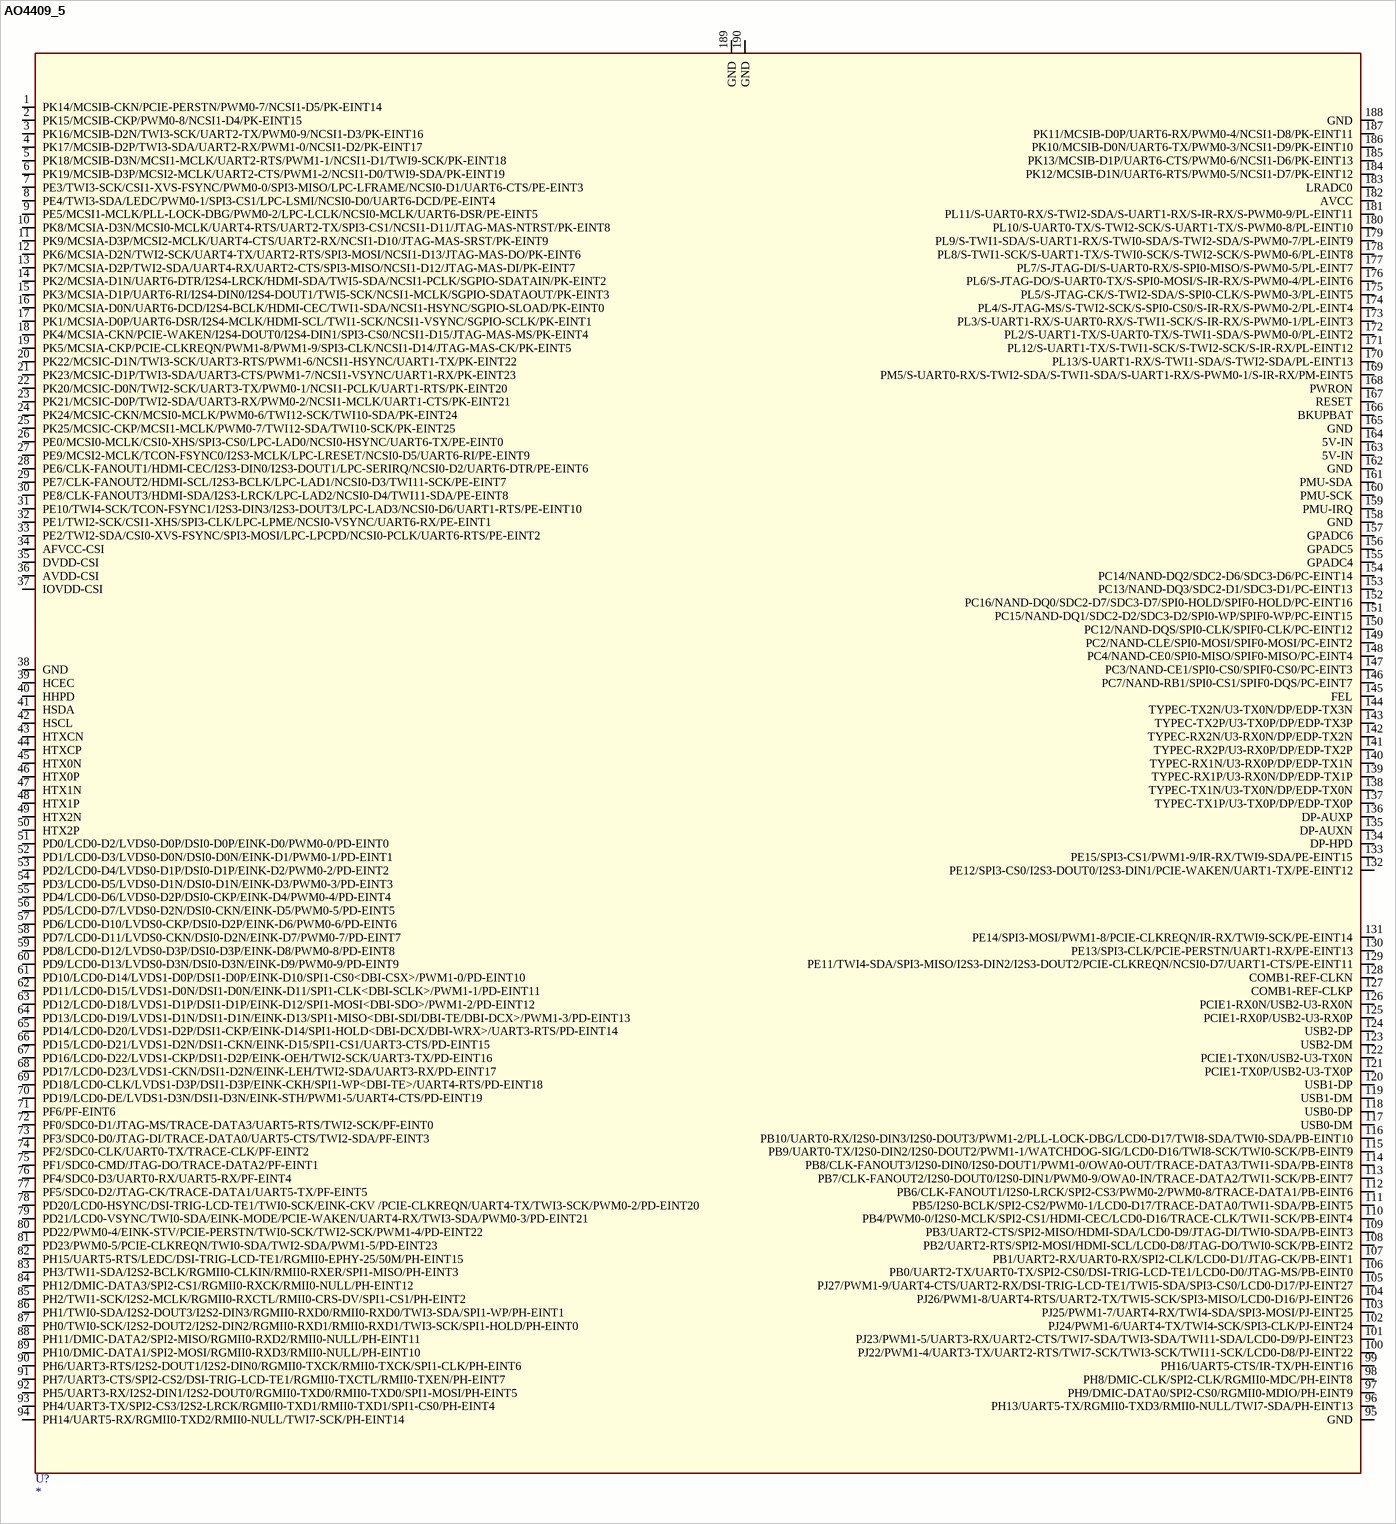
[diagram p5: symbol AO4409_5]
